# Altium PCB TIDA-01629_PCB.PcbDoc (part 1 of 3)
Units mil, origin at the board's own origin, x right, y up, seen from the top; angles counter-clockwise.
Board outline 2351.88 x 2559.06 mil, 4 copper layers (Top Layer, GND, POWER, Bottom Layer), stack 60.63 mil thick; 223 components, 122 nets, 655 pads, 542 vias.
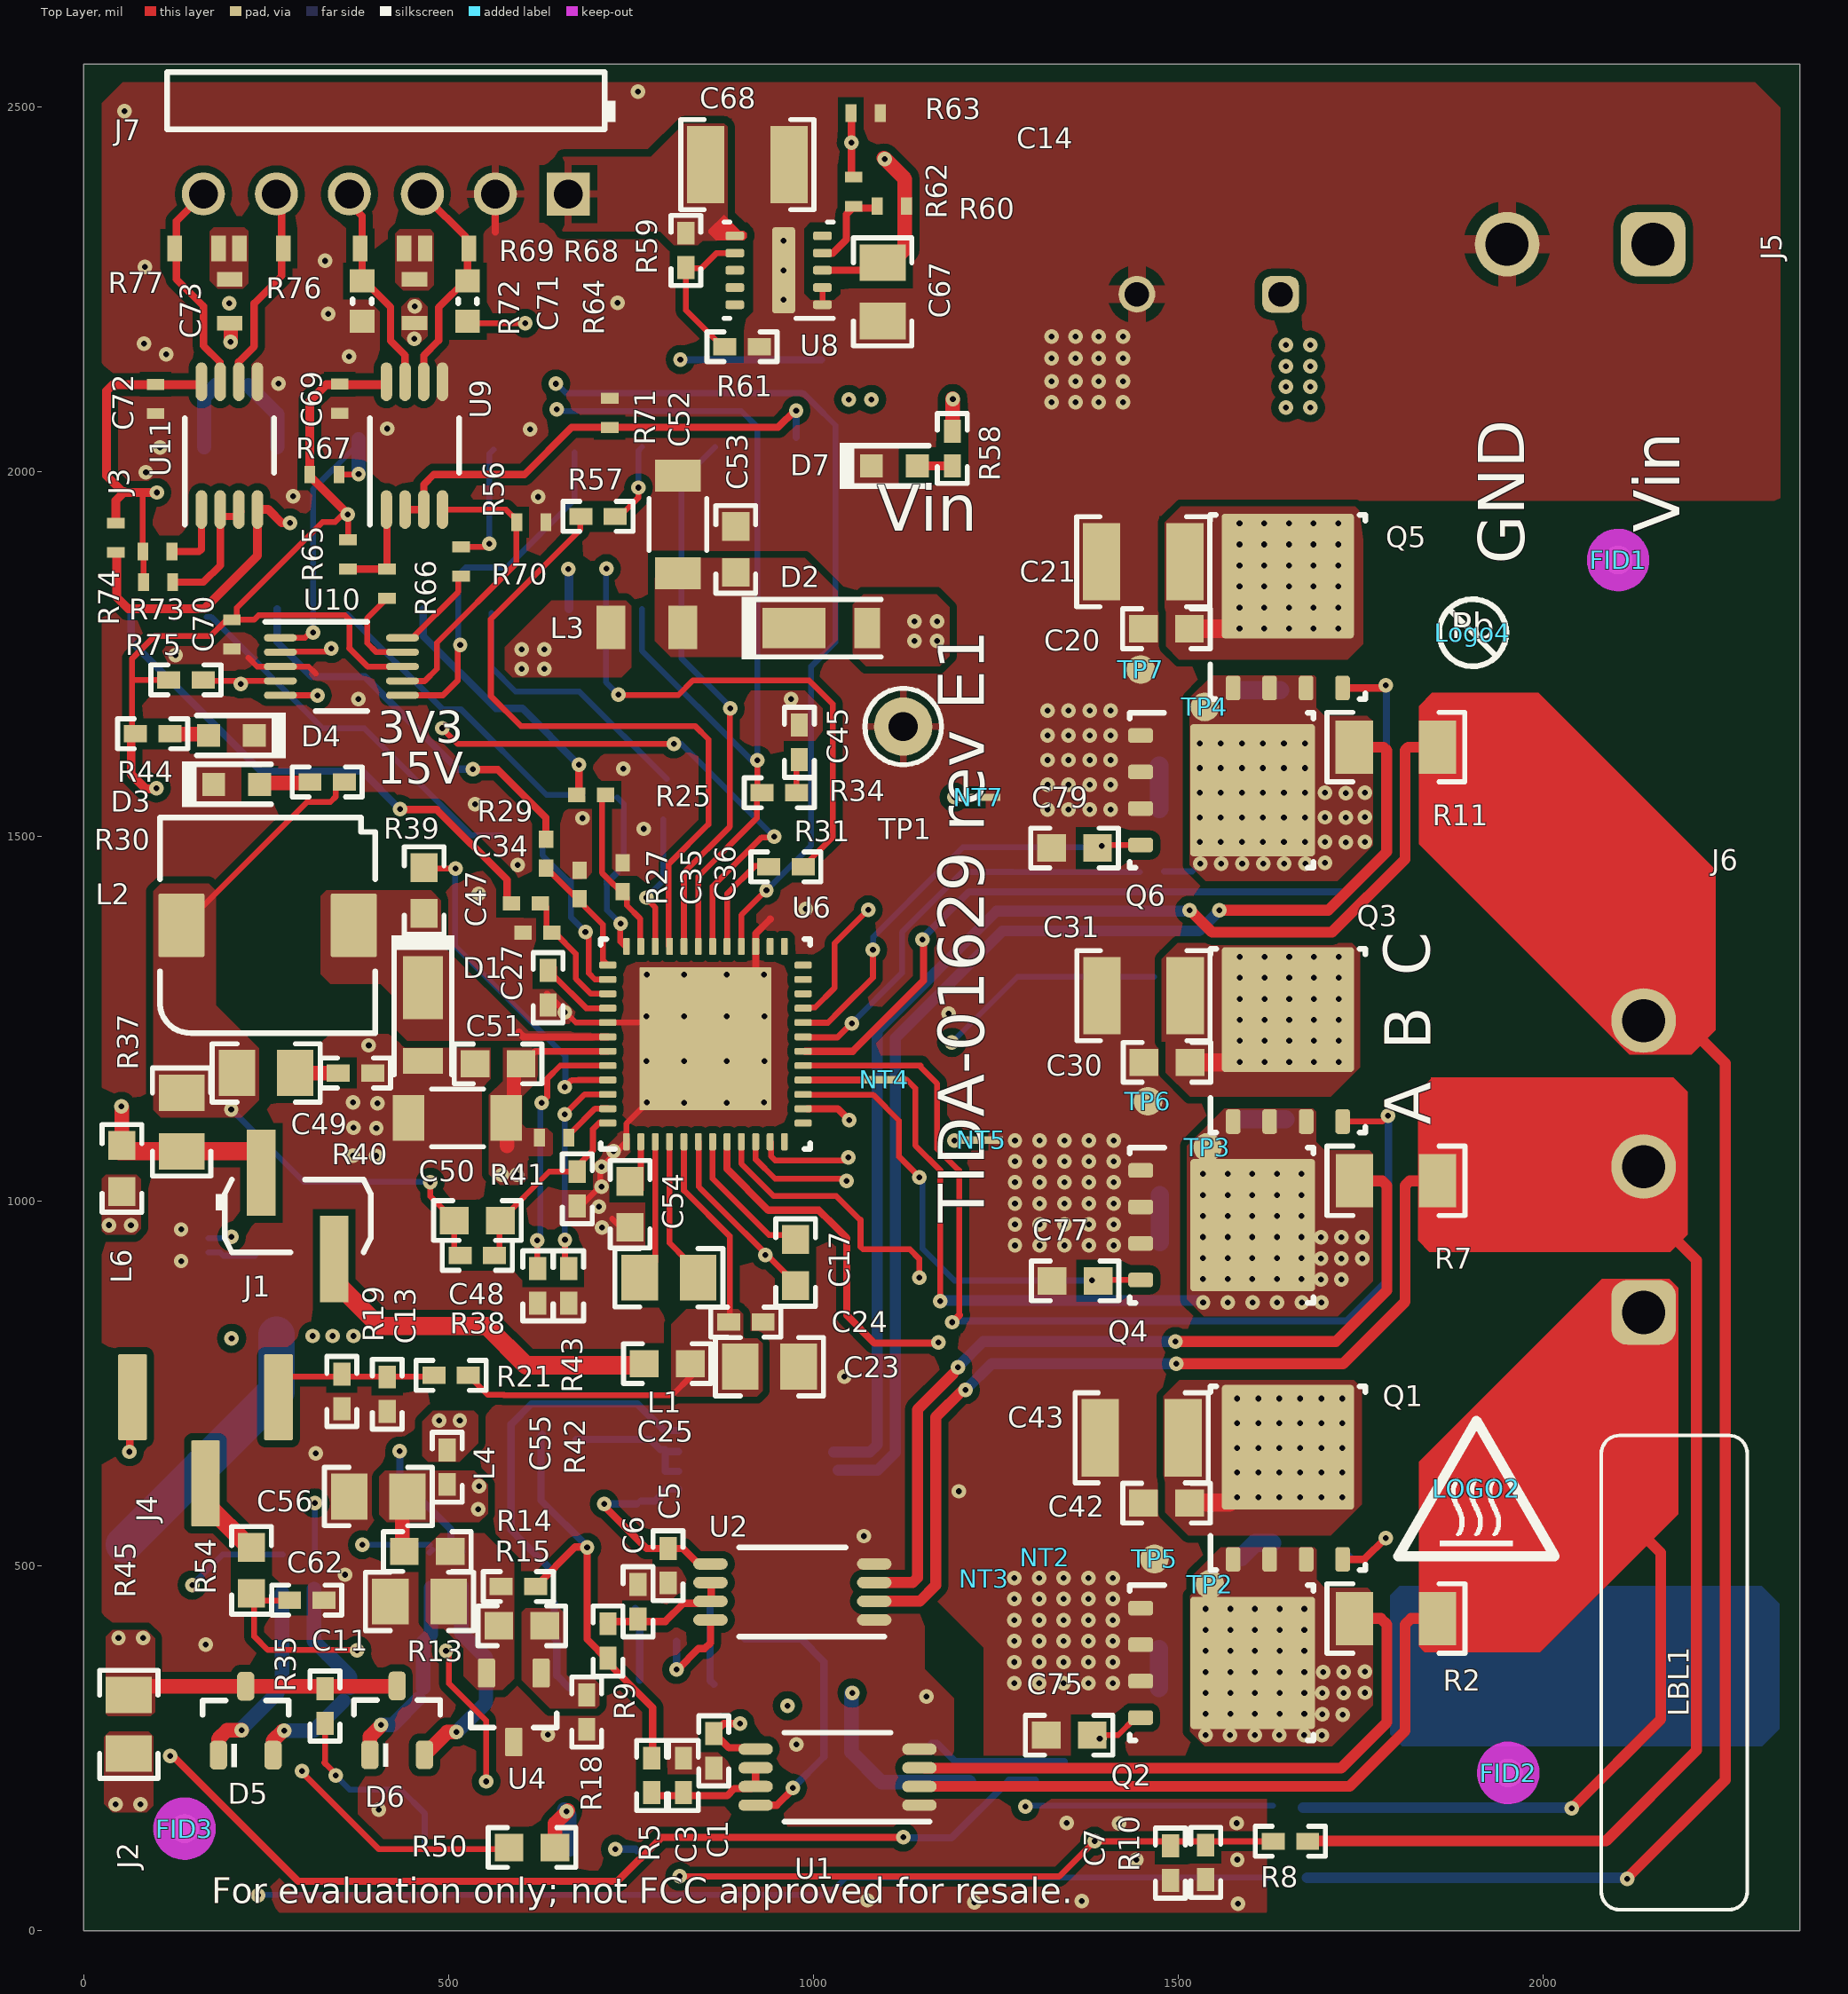
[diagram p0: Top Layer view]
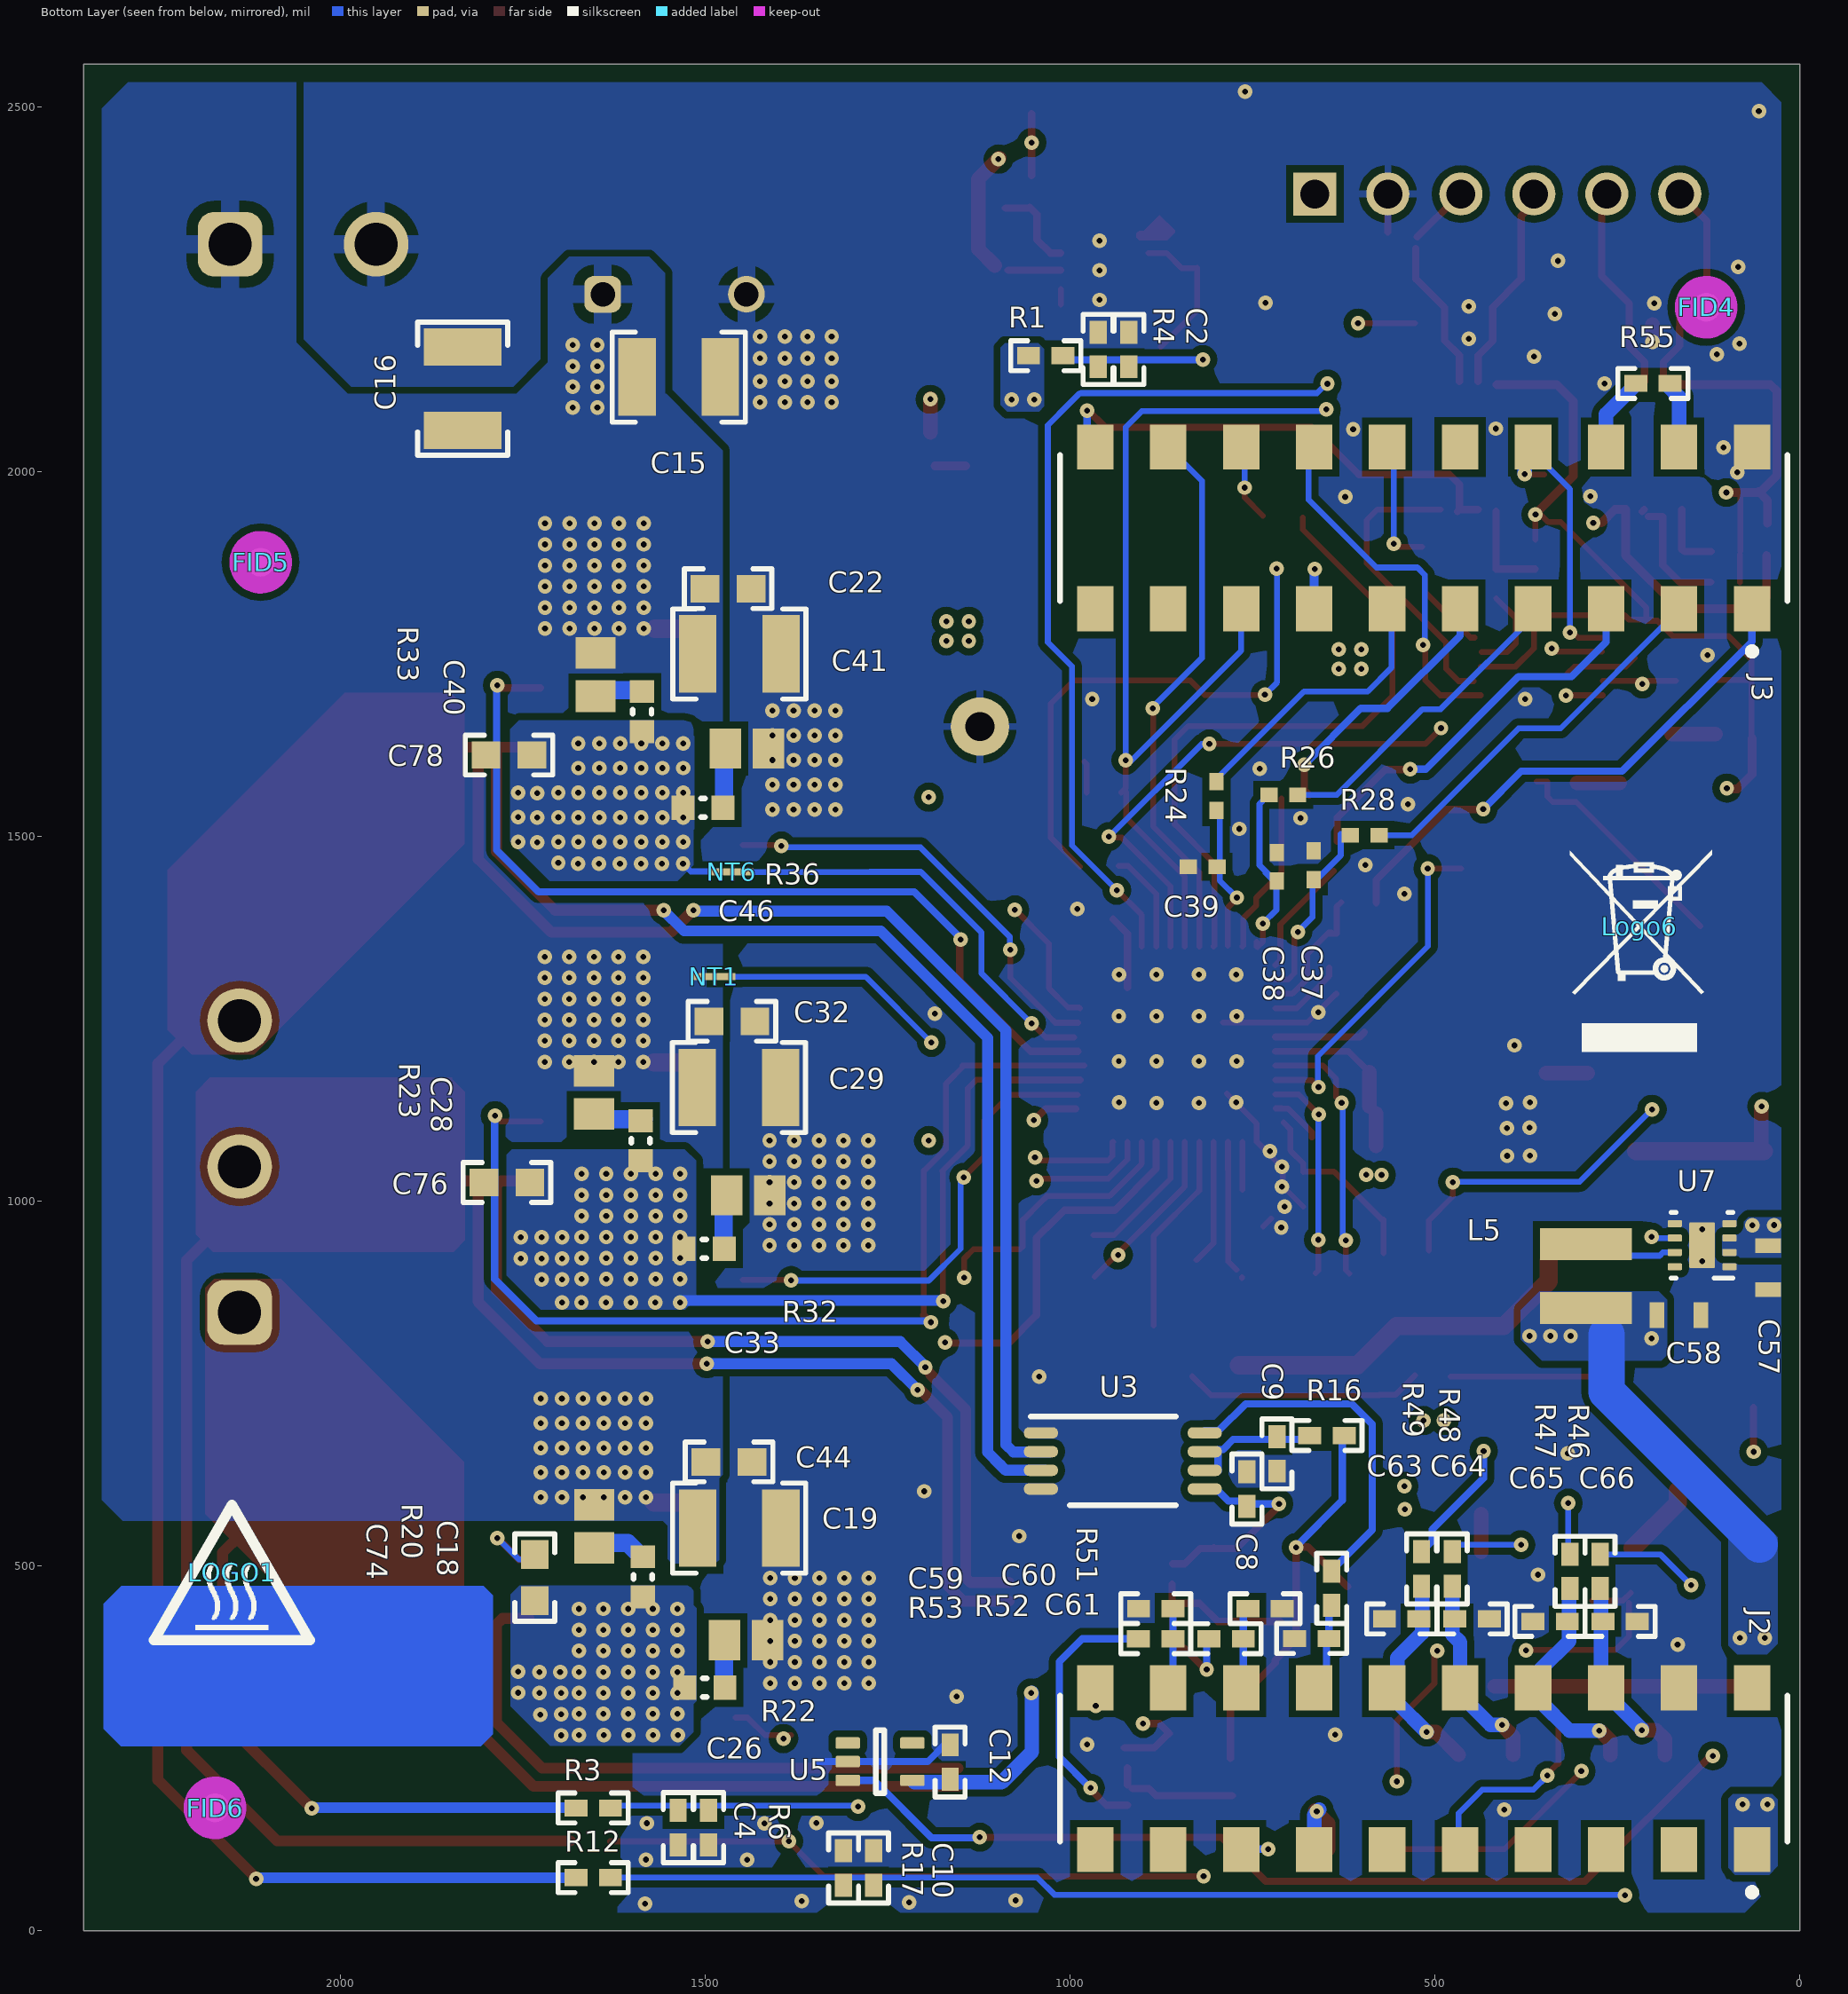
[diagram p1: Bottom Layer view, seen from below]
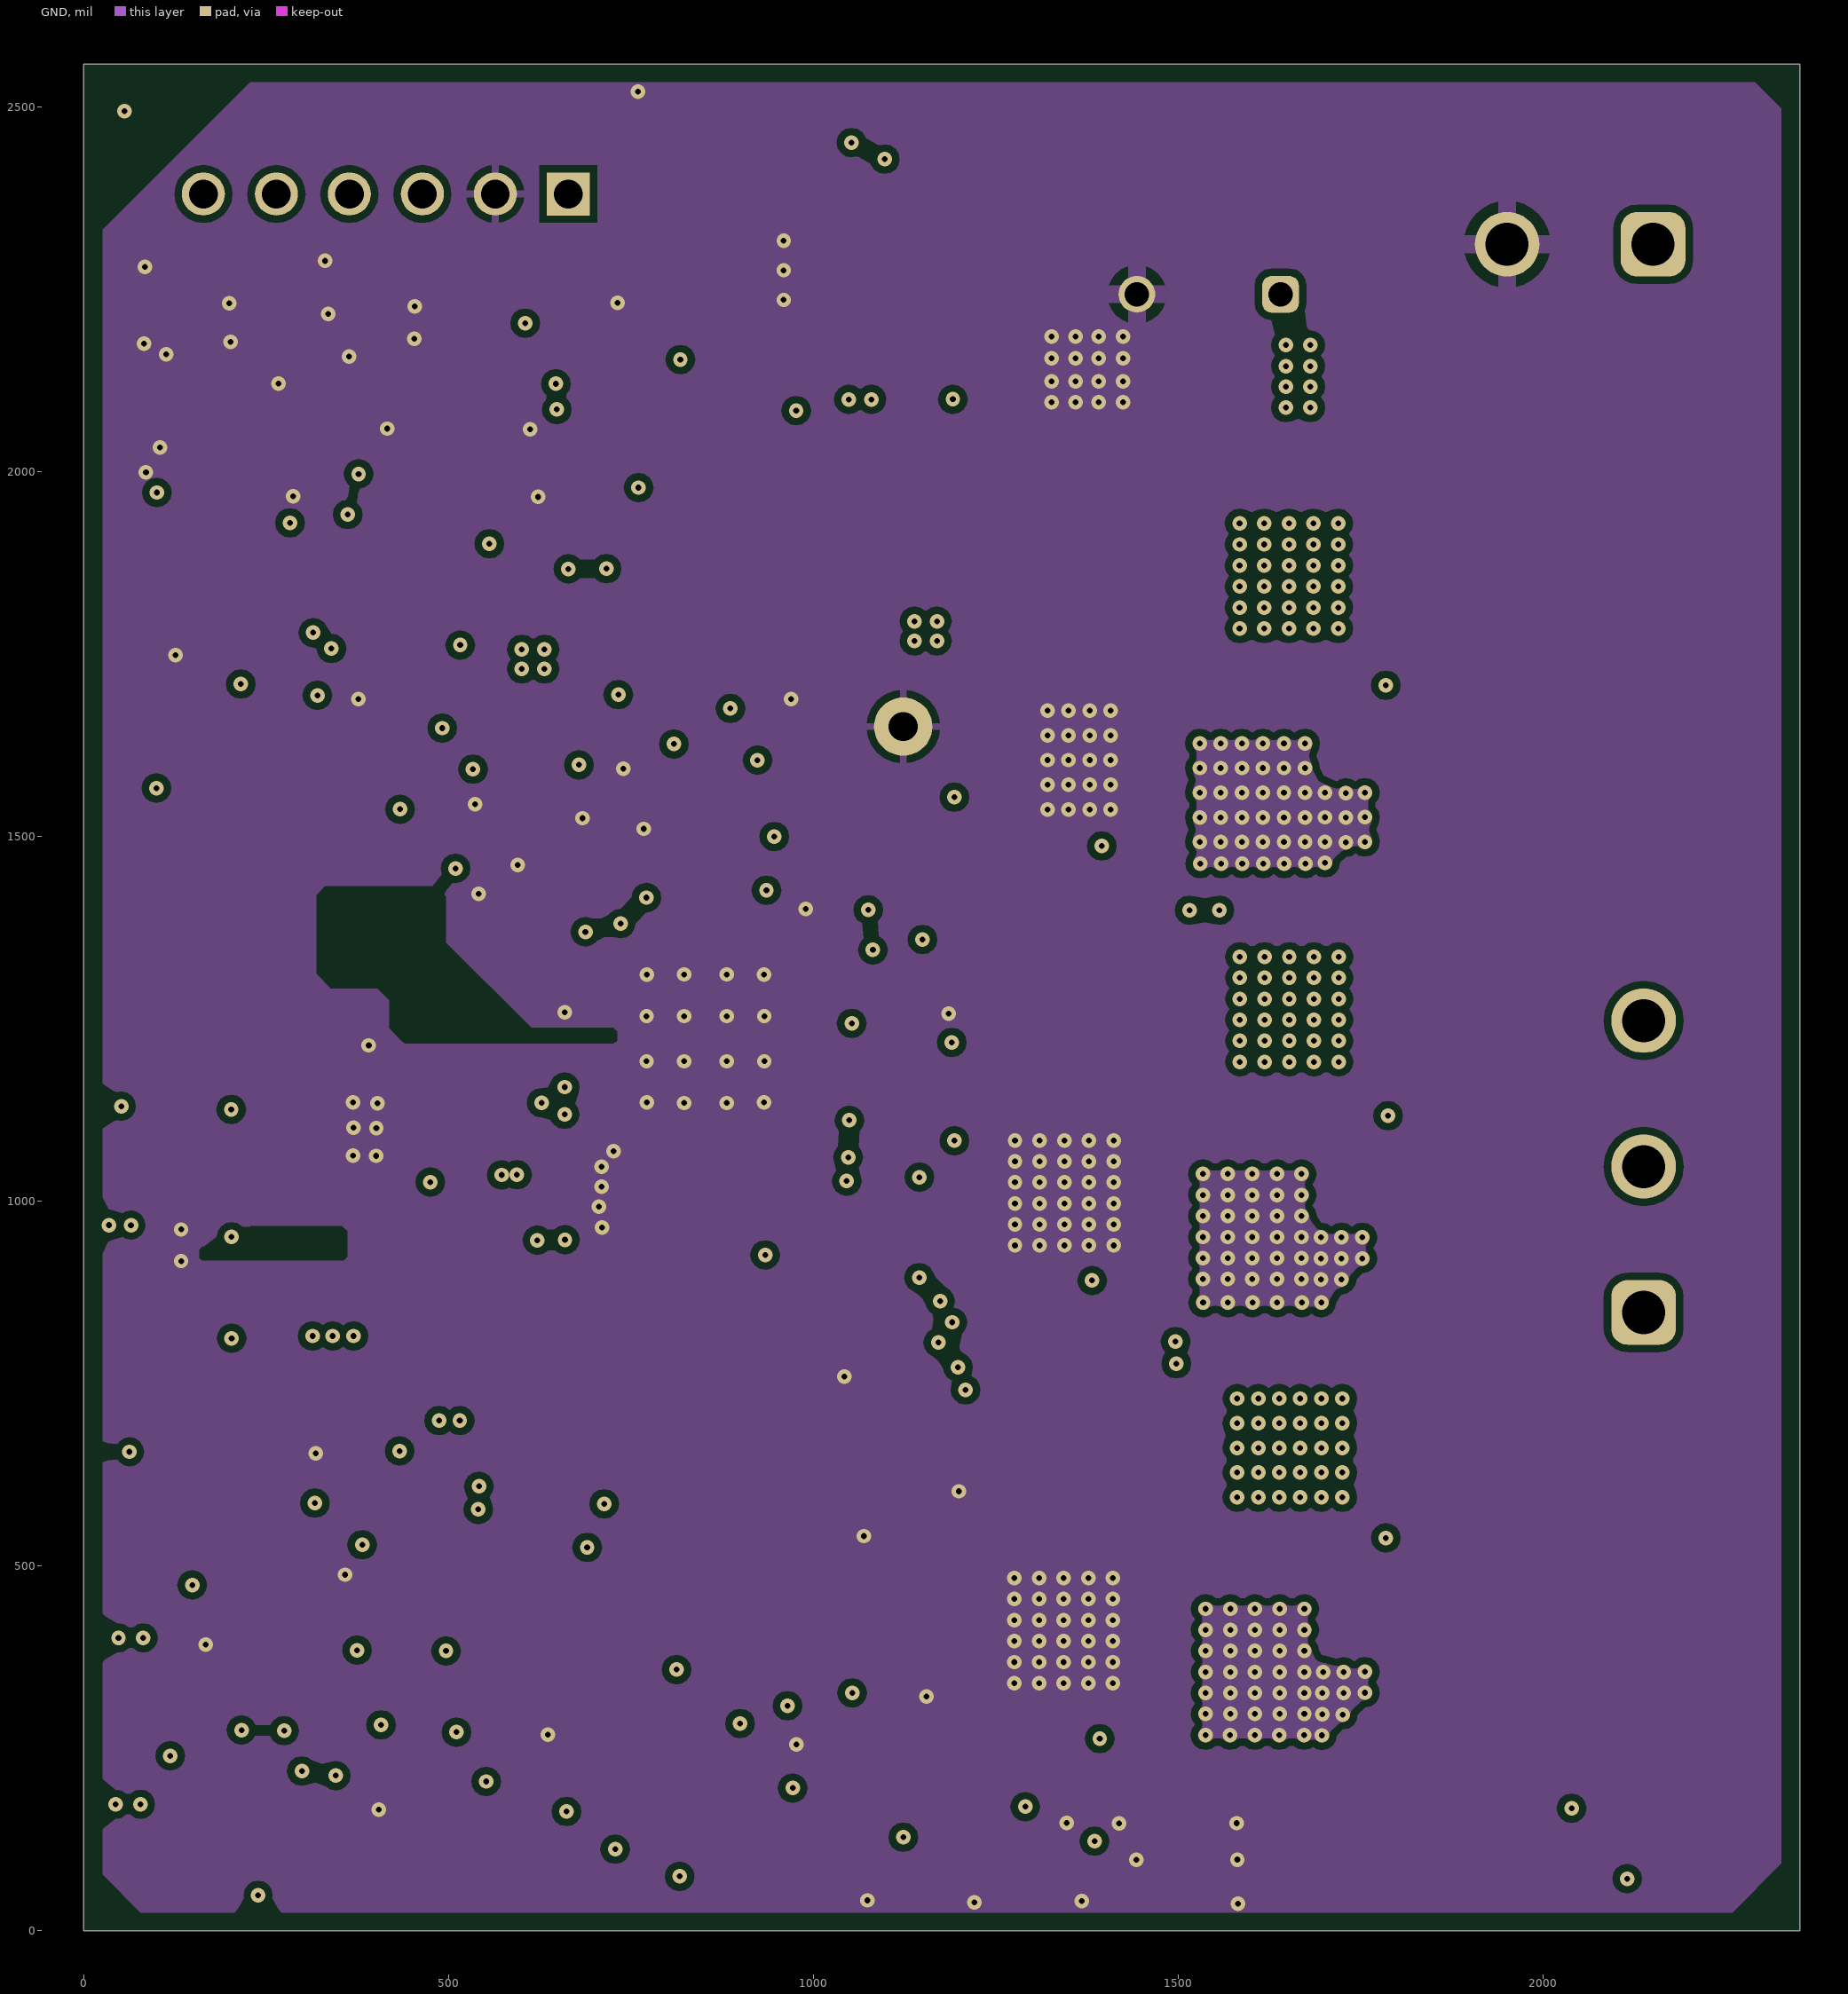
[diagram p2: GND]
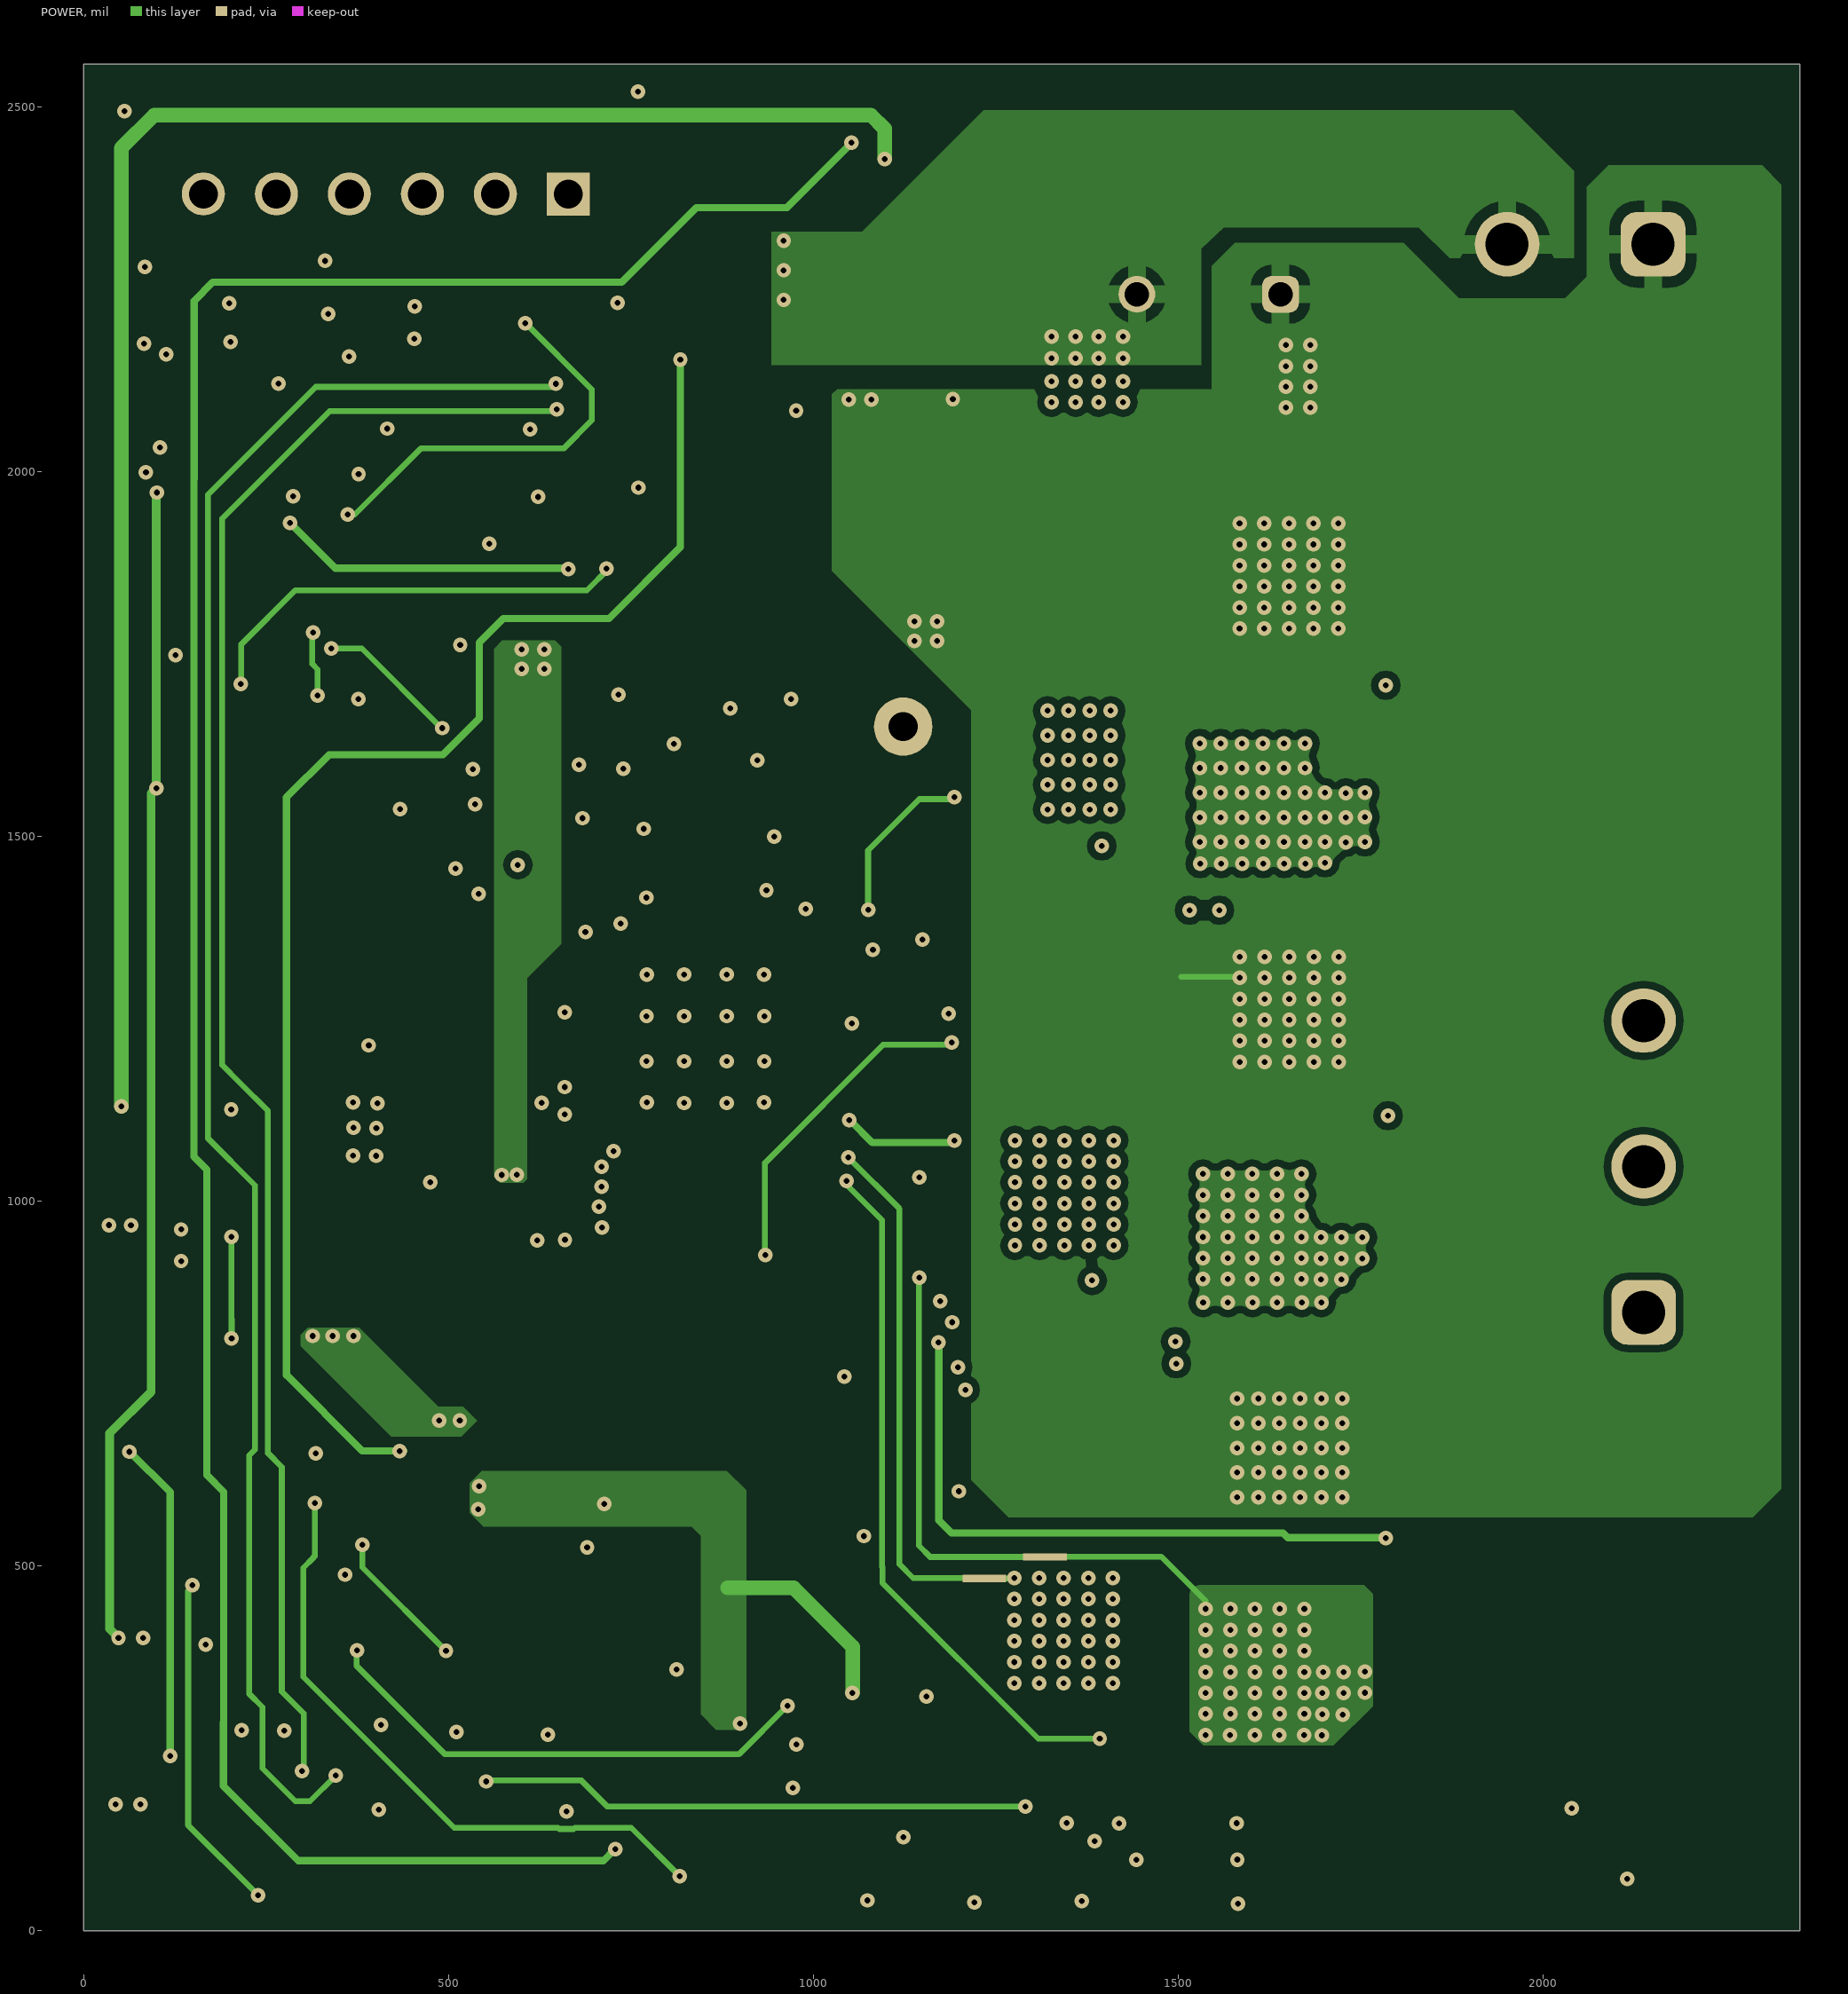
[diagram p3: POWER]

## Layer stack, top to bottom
Top Solder: solder mask 0.9843, Solder Resist, Dk 3.5
Top Layer: signal copper 2.7559
Dielectric 2: prepreg 14.9606, FR-4, Dk 4.2
GND: signal copper 2.7559
Dielectric1: core 19.685, FR-4, Dk 4.2
POWER: signal copper 2.7559
Dielectric 3: prepreg 14.9606, FR-4, Dk 4.2
Bottom Layer: signal copper 2.7559
Bottom Solder: solder mask 0.9843, Solder Resist, Dk 3.5

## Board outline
0,0 2351.88,0 2351.88,2559.06 0,2559.06

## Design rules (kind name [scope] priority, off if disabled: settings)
AcuteAngle [All] p1: minimum=6.90000000000000E+0001 checktracksonly=FALSE
AssemblyTestPointUsage [All] p1: valid=2
BoardOutlineClearance BoardOutlineClearance_MountingHoles [OnCopper and InComponentClass('Mounting Holes')] p1: gap=40 ignorepadtopadclearanceinfootprint=FALSE
BoardOutlineClearance BoardOutlineClearance_Poly [OnCopper and IsPoly] p2: gap=25 ignorepadtopadclearanceinfootprint=FALSE
BoardOutlineClearance [OnCopper and Not InComponentClass('Logo') and not InComponentClass('FiducialMark') and not InRegion(1000,500,4000,800) and not InPoly] p3: gap=25 ignorepadtopadclearanceinfootprint=FALSE
Clearance Clearance_TP [(ObjectKind = 'Component') And (Comment = 'TP_SM_1MM')] p1: gap=0 ignorepadtopadclearanceinfootprint=TRUE
Clearance Clearance_NetTie [(ObjectKind = 'Component') And (Comment = 'Net-Tie')] p2: gap=9.84 ignorepadtopadclearanceinfootprint=FALSE except(0: Arc-Hole Track-Hole SMDPad-Hole THPad-Hole Via-Hole Fill-Hole Poly-Hole Region-Hole Text-Hole)
Clearance Clearance_Keepouts [((IsTrack Or IsArc) And Not InPoly) And IsFree and IsKeepOut vs ((IsTrack Or IsArc) And Not InPoly) And IsFree and IsKeepOut] p3: gap=0 ignorepadtopadclearanceinfootprint=FALSE
Clearance Clearance_Poly [InPolygon] p4: gap=9.84 ignorepadtopadclearanceinfootprint=FALSE except(0: Arc-Hole Track-Hole SMDPad-Hole THPad-Hole Via-Hole Fill-Hole Poly-Hole Region-Hole Text-Hole)
Clearance Clearance_FiducialMark [IsKeepOut and InComponentClass('FiducialMark') vs IsPad and InComponentClass('FiducialMark')] p5: gap=0 ignorepadtopadclearanceinfootprint=FALSE
Clearance [All] p6: gap=9.84 ignorepadtopadclearanceinfootprint=FALSE except(0: Arc-Hole Track-Hole SMDPad-Hole THPad-Hole Via-Hole Fill-Hole Poly-Hole Region-Hole Text-Hole)
ComponentClearance ComponentClearance_MountingHoles_FiducialMarks [InComponentClass('Mounting Holes') vs InComponentClass('FiducialMark')] p1: gap=50 collisioncheckmode=3 verticalgap=10 showdistances=FALSE
ComponentClearance ComponentClearance_Shunt [InComponentClass('Header') vs InComponentClass('Shunt')] p2: gap=0 collisioncheckmode=3 verticalgap=0 showdistances=FALSE
ComponentClearance ComponentClearance_Logo [InComponentClass('Logo')] p3: gap=50 collisioncheckmode=3 verticalgap=10 showdistances=FALSE
ComponentClearance ComponentClearance_ScrewToNut [(HasFootprint('NY PMS 440 0025 PH')) vs (HasFootprint('Keystone_1902C'))] p4: gap=5 collisioncheckmode=3 verticalgap=10 showdistances=FALSE
ComponentClearance ComponentClearance_MountingHoles [InComponentClass('Mounting Holes')] p5: gap=250 collisioncheckmode=3 verticalgap=100000 showdistances=FALSE
ComponentClearance ComponentClearance_SmallPassives [HasFootprint('0201*') or HasFootprint('0402*') or HasFootprint('0508') or HasFootprint('0603*') or HasFootprint('0612') or HasFootprint('0805*') or HasFootprint('0815*') or HasFootprint('0830*') or HasFootprint('1206*') or HasFootprint('1210*') or HasFootprint('1808*') or HasFootprint('1812*') or HasFootprint('1825*') or HasFootprint('2010*') or HasFootprint('2220*') or HasFootprint('2225*') or HasFootprint('2512*') or HasFootprint('2728*') or HasFootprint('3518*') vs HasFootprint('0201*') or HasFootprint('0402*') or HasFootprint('0508') or HasFootprint('0603*') or HasFootprint('0612') or HasFootprint('0805*') or HasFootprint('0815*') or HasFootprint('0830*') or HasFootprint('1206*') or HasFootprint('1210*') or HasFootprint('1808*') or HasFootprint('1812*') or HasFootprint('1825*') or HasFootprint('2010*') or HasFootprint('2220*') or HasFootprint('2225*') or HasFootprint('2512*') or HasFootprint('2728*') or HasFootprint('3518*')] p6: gap=14.96 collisioncheckmode=3 verticalgap=10 showdistances=FALSE
ComponentClearance ComponentClearance_THtoSMT [IsThruComponent vs IsSMTComponent] p7: gap=40 collisioncheckmode=3 verticalgap=30 showdistances=FALSE
ComponentClearance ComponentClearance_THtoTH [IsThruComponent vs IsThruComponent] p8: gap=30 collisioncheckmode=3 verticalgap=30 showdistances=FALSE
ComponentClearance ComponentClearance_TP [(ObjectKind = 'Component') And (Comment = 'TP_SM_1MM')] p9: gap=0 collisioncheckmode=3 verticalgap=0 showdistances=FALSE
ComponentClearance [All] p10: gap=30 collisioncheckmode=3 verticalgap=10 showdistances=FALSE
DiffPairsRouting [All] p1 off: maxlimit=100 minlimit=10 mostfreqgap=10 toplayer_minwidth=7 toplayer_maxwidth=25 toplayer_prefwidth=15 midlayer1_minwidth=7 midlayer1_maxwidth=25 midlayer1_prefwidth=15 midlayer2_minwidth=7 midlayer2_maxwidth=25 midlayer2_prefwidth=15 bottomlayer_minwidth=7 bottomlayer_maxwidth=25 bottomlayer_prefwidth=15 maxuncoupledlength=1000
FabricationTestPointUsage TestPointUsage [All] p1: valid=2 allowmultiple=FALSE
FabricationTestpoint Testpoint [All] p1: side=3 testpointundercomponent=TRUE minsize=40 maxsize=100 preferedsize=60 minholesize=0 maxholesize=40 preferedholesize=32 testpointgrid=1 allowsidetop=TRUE allowsidebottom=TRUE usegrid=TRUE gridtolerance=0.01
FanoutControl Fanout_LCC [IsLCC] p1: bgadir=Out bgaviamode=Centered fanoutstyle=Auto fanoutdirection=Alternating viagrid=1 // Fanout_LCC (Default Rule)
FanoutControl Fanout_BGA [IsBGA] p2: bgadir=Out bgaviamode=Centered fanoutstyle=Auto fanoutdirection=Alternating viagrid=1 // Fanout_BGA (Default Rule)
FanoutControl Fanout_Default [All] p4: bgadir=Out bgaviamode=Centered fanoutstyle=Auto fanoutdirection=Alternating viagrid=1 // Fanout_Default (Default Rule)
FanoutControl Fanout_Small [(CompPinCount < 5)] p5: bgadir=Out bgaviamode=Centered fanoutstyle=Auto fanoutdirection=OutThenIn viagrid=1 // Fanout_Small (Default Rule)
Height [All] p1: minheight=0 maxheight=1050 prefheight=500
HoleSize [All] p1: absolutevalues=TRUE maxlimit=251 minlimit=7.87 maxpercent=80.000 minpercent=20.000
MinimumAnnularRing MinimumAnnularRing_ThermalPadVias [IsVia and InAnyComponent] p1: minimumring=5.91
MinimumAnnularRing [All] p2: minimumring=5.91
MinimumSolderMaskSliver MinimumSolderMaskSliver_Logo [InComponentClass('Logo') vs InComponentClass('Logo')] p1: minsoldermaskwidth=0.7
MinimumSolderMaskSliver [All] p2: minsoldermaskwidth=2.72
PlaneConnect [All] p1: planeconnectstyle=Relief reliefexpansion=10 reliefentries=4 reliefconductorwidth=10 reliefairgap=10
PolygonConnect "Thermal Connect" [IsVia] p1 off: thpad.connectstyle=Relief thpad.reliefconductorwidth=10 thpad.reliefentries=4 thpad.polygonreliefangle="90 Angle" thpad.airgapwidth=10 smdpad.connectstyle=Direct smdpad.reliefconductorwidth=10 smdpad.reliefentries=4 smdpad.polygonreliefangle="90 Angle" smdpad.airgapwidth=10 via.connectstyle=Direct via.reliefconductorwidth=10 via.reliefentries=4 via.polygonreliefangle="90 Angle" via.airgapwidth=10
PolygonConnect PolygonConnect_Thermal [((ObjectKind = 'Poly') And ((Net = 'PH_C_P') or (Net = 'PH_B_P') or (Net = 'PH_A_P') or (Name = 'BOTTOM_LAYER_VIN_P286') or (Name = 'BOTTOM_LAYER_VIN_P284') or (Name = 'POWER_VIN_P288') or (Name = 'POWER_VIN_P294') or (Name = 'THERMAL_GND')))] p2 off: connectstyle=Relief reliefconductorwidth=20 reliefentries=4 polygonreliefangle="90 Angle" airgapwidth=10
PolygonConnect "Thermal Connect_HighCurrent" [IsThruPin and InComponent('C14','J5')] p3: connectstyle=Relief reliefconductorwidth=25 reliefentries=4 polygonreliefangle="90 Angle" airgapwidth=15
PolygonConnect [All] p4: thpad.connectstyle=Relief thpad.reliefconductorwidth=10 thpad.reliefentries=4 thpad.polygonreliefangle="90 Angle" thpad.airgapwidth=10 smdpad.connectstyle=Direct smdpad.reliefconductorwidth=10 smdpad.reliefentries=4 smdpad.polygonreliefangle="90 Angle" smdpad.airgapwidth=10 via.connectstyle=Direct via.reliefconductorwidth=10 via.reliefentries=4 via.polygonreliefangle="90 Angle" via.airgapwidth=10
RoutingVias ThermalPadVias [IsVia and InAnyComponent] p1: holewidth=7.87 width=19.68 viastyle="Through Hole" minholewidth=7.87 minwidth=19.68 maxholewidth=12.99 maxwidth=23.62
RoutingVias [All] p2: holewidth=16 width=34 viastyle="Through Hole" minholewidth=7.87 minwidth=19.68 maxholewidth=40 maxwidth=65
SilkToBoardRegionClearance [Not ((IsComment or IsDesignator) And (Hide <> 'False')) and not InRegion(1000,500,4000,800)] p1:
SilkToSilkClearance SilkToSilkClearance_Pb-FreeLogo [(HasFootprint('Pb-Free_Overlay_Medium') OR HasFootprint('Pb-Free_Overlay_Small')) vs (HasFootprint('Pb-Free_Overlay_Medium') OR HasFootprint('Pb-Free_Overlay_Small'))] p1: silktosilkclearance=0
SilkToSilkClearance [All] p2: silktosilkclearance=4
SilkToSolderMaskClearance SilkToComponentPadClearance [(IsPad or IsFill or IsRegion) and InAnycomponent] p1: minsilkscreentomaskgap=5 clearancetoexposedcopper=TRUE
SilkToSolderMaskClearance "Silk to Solder Mask Opening" [All] p2: minsilkscreentomaskgap=4 clearancetoexposedcopper=FALSE
SolderMaskExpansion [All] p1: expansion=1.97
Width [All] p1: maxlimit=100 minlimit=7.87 preferedwidth=10 checkconnectedcopper=TRUE
14 further rules are at their usual default settings.

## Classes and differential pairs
component class TIDA-01629_EVM_Hardware: FID1 FID2 FID3 FID4 FID5 FID6 LBL1 LOGO1 LOGO2 Logo4 Logo5 Logo6 ZZ1 ZZ2 ZZ3 ZZ4
component class FiducialMark: FID1 FID2 FID3 FID4 FID5 FID6
component class AssemblyNote: ZZ1 ZZ2 ZZ3 ZZ4
component class Label: LBL1
component class Header: J1 J4 J7
component class TIDA-01629_CurrentSense: C1 C2 C3 C4 C5 C6 C7 C8 C9 C10 C11 C12 R1 R2 R3 R4 R5 R6 R7 R8 R9 R10 R11 R12 R13 R14 R15 R16 R17 R18 U1 U2 U3 U4 U5
component class TIDA-01629_Gate_Driver: C13 C14 C15 C16 C17 C18 C19 C20 C21 C22 C23 C24 C25 C26 C27 C28 C29 C30 C31 C32 C33 C34 C35 C36 C37 C38 C39 C40 C41 C42 C43 C44 C45 C46 C47 C48 C49 C50 C51 C52 C53 C54 C55 C56 C57 C58 C74 C75 C76 C77 C78 C79 D1 D2 D3 D4 J1 L1 L2 L3 L4 L5 L6 NT1 NT2 NT3 NT4 NT5 NT6 NT7 Q1 Q2 Q3 Q4 Q5 Q6 R19 R20 R21 R22 R23 R24 R25 R26 R27 R28 R29 R30 R31 R32 R33 R34 R35 R36 R37 R38 R39 R40 R41 R42 R43 R44 TP1 TP2 TP3 TP4 TP5 TP6 TP7 TP? U6 U7
component class TIDA-01629_Interface: C59 C60 C61 C62 C63 C64 C65 C66 D5 D6 D7 J2 J3 J4 J5 J6 R45 R46 R47 R48 R49 R50 R51 R52 R53 R54 R55 R56 R57 R58
component class TIDA-01629_Encoder: C67 C68 C69 C70 C71 C72 C73 J7 R59 R60 R61 R62 R63 R64 R65 R66 R67 R68 R69 R70 R71 R72 R73 R74 R75 R76 R77 U8 U9 U10 U11
differential pair PH_C: +PH_C_P -PH_C_N
differential pair PH_B: +PH_B_P -PH_B_N
differential pair PH_A: +PH_A_P -PH_A_N
differential pair CLK: +CLK_P -CLK_N
differential pair DATA: +DATA_P -DATA_N

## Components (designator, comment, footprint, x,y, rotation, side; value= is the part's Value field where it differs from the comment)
C1 "885012205037" 0402 863.72,247 r270 top value=0.1uF
C2 "GRM155R71A104KA01D" 0402 919.24,2167.56 r90 bottom value=0.1uF
C3 "885012205037" 0402 822.2,213.25 r90 top value=0.1uF
C4 "GRM155R71A104KA01D" 0402 1536.97,141.62 r270 bottom value=0.1uF
C5 "885012205037" 0402 801,500.66 r270 top value=0.1uF
C6 "885012205037" 0402 759.93,451.14 r90 top value=0.1uF
C7 "GRM155R71A104KA01D" 0402 1489.46,93.06 r270 top value=0.1uF
C8 "885012205037" 0402 757.42,605.64 r90 bottom value=0.1uF
C9 "885012205037" 0402 716.52,653.91 r270 bottom value=0.1uF
C10 "GRM155R71A104KA01D" 0402 1269.15,86.27 r90 bottom value=0.1uF
C11 "885012207103" 0805_HV 460.53,451.64 r180 top value=1uF
C12 "885012205037" 0402 1164.21,231.51 r90 bottom value=0.1uF
C13 "GCM155R71H223KA55D" 0402 416.26,735.68 r90 top value=0.022uF
C14 "EKYB101ELL181MK20S" KYB_1250x2000 1541.92,2243.25 r180 top value=180uF
C15 "GRM32ER72A105KA01L" 1210_270 1536.16,2129.83 r180 bottom value=1uF
C16 "GRM32ER72A105KA01L" 1210_270 1832.33,2114.02 r90 bottom value=1uF
C17 "GRM188R61H105KAALD" 0603 975.86,916.1 r270 top value=1uF
C18 "GRM188R72A222KA01D" 0603L 1585.43,485.38 r270 bottom value=2200pF
C19 "GRM32ER72A225KA35L" 1210_270 1453.27,552.19 r180 bottom value=2.2uF
C20 "GRM188R72A104KA35J" 0603 1484.02,1784.92 r180 top value=0.1uF
C21 "GRM32ER72A225KA35L" 1210_270 1452.15,1876.71 r180 top value=2.2uF
C22 "GRM188R72A104KA35J" 0603 1468.56,1839.62 r180 bottom value=0.1uF
C23 "GRM21BZ71E106KE15L" 0805_HV 940.05,773.41 r0 top value=10uF
C24 "GRM155R71E104KE14D" 0402 907.72,834.44 r0 top value=0.1uF
C25 "GRM21BR72A473KA01L" 0805_HV 802.35,895.47 r180 top value=0.047uF
C26 "GRM188R72A222KA01D" 0603L 1500.35,333.63 r180 bottom value=2200pF
C27 "GRM155R70J105MA12D" 0402 636.72,1293.01 r270 top value=1uF
C28 "GRM188R72A222KA01D" 0603L 1588.47,1083.09 r270 bottom value=2200pF
C29 "GRM32ER72A225KA35L" 1210_270 1453.54,1156.05 r180 bottom value=2.2uF
C30 "GRM188R72A104KA35J" 0603 1484.8,1190.55 r180 top value=0.1uF
C31 "GRM32ER72A225KA35L" 1210_270 1452.65,1282.02 r180 top value=2.2uF
C32 "GRM188R72A104KA35J" 0603 1463.26,1246.82 r180 bottom value=0.1uF
C33 "GRM188R72A222KA01D" 0603L 1501.28,935.11 r180 bottom value=2200pF
C34 "885012005044" 0402L 622.11,1368.42 r180 top value=47pF
C35 "885012005044" 0402L 680.06,1434.3 r90 top value=47pF
C36 "885012005044" 0402L 738.93,1444.5 r90 top value=47pF
C37 "885012005044" 0402L 666.21,1460.65 r90 bottom value=47pF
C38 "885012005044" 0402L 716.64,1458.61 r90 bottom value=47pF
C39 "885012005044" 0402L 818.18,1458.58 r0 bottom value=47pF
C40 "GRM188R72A222KA01D" 0603L 1586.25,1671.25 r270 bottom value=2200pF
C41 "GRM32ER72A225KA35L" 1210_270 1453.02,1750.34 r180 bottom value=2.2uF
C42 "GRM188R72A104KA35J" 0603 1484.19,586.51 r180 top value=0.1uF
C43 "GRM32ER72A225KA35L" 1210_270 1450.11,675.87 r180 top value=2.2uF
C44 "GRM188R72A104KA35J" 0603 1467.25,642.91 r180 bottom value=0.1uF
C45 "885012005061" 0402 980.97,1629.17 r90 top value=100pF
C46 "GRM188R72A222KA01D" 0603L 1502.87,1539.6 r180 bottom value=2200pF
C47 "GRM188R72A103KA01D" 0603 466.82,1426.13 r90 top value=0.01uF
C48 "GRM1885C1H302JA01D" 0603 539.82,973.77 r0 top value=3000pF
C49 "C2012X7R1H225K125AC" 0805_HV 250.31,1176.07 r0 top value=2.2uF
C50 "Capacitor" 1206_190 512.55,1114.42 r180 top value=3.3uF
C51 "GRM188R72A104KA35J" 0603 568.1,1188.58 r180 top value=0.1uF
C52 "Capacitor" 1206_190 814.65,1927.83 r90 top value=3.3uF
C53 "Capacitor" 0603 893.94,1893.57 r90 top value=0.1uF
C54 "UMK107AB7105KA-T" 0603 748.98,996.08 r270 top value=1uF
C55 "885012205037" 0402 622.66,884.33 r270 top value=0.1uF
C56 "885012207026" 0805_HV 404.1,595.46 r180 top value=10uF
C57 "Capacitor" 0603S 43.33,909.13 r270 bottom value=10uF
C58 "Capacitor" 0603S 165.53,843.98 r180 bottom value=22uF
C59 "GRM155R71C222KA01D" 0402 882.46,441.81 r0 bottom value=2200pF
C60 "GRM155R71C222KA01D" 0402 732.72,441.81 r180 bottom value=2200pF
C61 "GRM155R71C222KA01D" 0402 668.77,400.81 r0 bottom value=2200pF
C62 "GRM155R71C222KA01D" 0402 306.05,453.54 r0 top value=2200pF
C63 "GRM155R71C222KA01D" 0402 545.46,427.68 r0 bottom value=2200pF
C64 "GRM155R71C222KA01D" 0402 449.11,427.68 r180 bottom value=2200pF
C65 "GRM155R71C222KA01D" 0402 342.18,424.36 r0 bottom value=2200pF
C66 "GRM155R71C222KA01D" 0402 246.16,424.34 r180 bottom value=2200pF
C67 "GRM21BZ71E106KE15L" 0805_HV 1095.22,2246.68 r270 top value=10uF
C68 "GRM32ER71E226KE15L" 1210_270 909.88,2421.05 r0 top value=22uF
C69 "Capacitor" 0402S 351.06,2100.23 r270 top value=0.1uF
C70 "Capacitor" 0402S 203.34,1777.12 r270 top value=0.1uF
C71 "Capacitor" 0603S 453.51,2233.9 r270 top value=470pF
C72 "Capacitor" 0402S 98.82,2099.87 r270 top value=0.1uF
C73 "Capacitor" 0603S 200.26,2233.58 r270 top value=470pF
C74 "GRM1885C1E102JA01D" 0603 1733.44,484.45 r270 bottom value=1000pF
C75 "GRM1885C1E102JA01D" 0603 1350.75,268.5 r180 top value=1000pF
C76 "GRM1885C1E102JA01D" 0603 1771.61,1025.88 r180 bottom value=1000pF
C77 "GRM1885C1E102JA01D" 0603 1358.82,890.99 r180 top value=1000pF
C78 "GRM1885C1E102JA01D" 0603 1768.73,1611.75 r180 bottom value=1000pF
C79 "GRM1885C1E102JA01D" 0603 1358.07,1484.37 r180 top value=1000pF
D1 "DFLS1200-7" PowerDI123 465.22,1242.57 r270 top value=200V
D2 "DFLS1200-7" PowerDI123 1023.78,1785.66 r0 top value=200V
D3 "LED_A2_K1" WL-SMCW_GREEN 209.99,1571.67 r0 top value=Green
D4 "LED_A2_K1" WL-SMCW_GREEN 202.77,1638.67 r180 top value=Green
D5 "BAT54C-7-F" SOT-23 222.39,288.3 r90 top value=30V
D6 "BAT54C-7-F" SOT-23 429.9,288.69 r90 top value=30V
D7 "LED_A2_K1" WL-SMCW_GREEN 1111.28,2007.97 r0 top value=Green
FID1 "Fiducial" Fiducial10-20 2102.95,1879.01 r0 top
FID2 "Fiducial" Fiducial10-20 1952.46,216.69 r0 top
FID3 "Fiducial" Fiducial10-20 138.34,140.32 r0 top
FID4 "Fiducial" Fiducial10-20 128.33,2225.51 r180 bottom
FID5 "Fiducial" Fiducial10-20 2109.14,1875.96 r180 bottom
FID6 "Fiducial" Fiducial10-20 2171.61,168.81 r180 bottom
J1 "61000218321" Wurth_61000218321 293.61,980.04 r0 top
J2 "89898-310ALF" FCI_89898-310ALF 515.44,222.45 r0 bottom
J3 "89898-310ALF" FCI_89898-310ALF 515.44,1923.03 r0 bottom
J4 "61000318221" Wurth_61000318221 167.25,676.49 r270 top
J5 "691236510002" Wurth_691236510002 2050.87,2311.85 r180 top
J6 "691236510003" Wurth_691236510003 2137.89,1047.77 r90 top
J7 "90121-0766" Molex_90121-0766 414.41,2380.76 r180 top
L1 "742792620" 0603 799.94,777.55 r0 top value="100 ohm"
L2 "MSS7348-224MEB" MSS7348 252.37,1378.41 r180 top value=220uH
L3 "Inductor_Iron" NLCV25 771.97,1786.75 r180 top value=33uH
L4 "742792711" 0402 498.62,635.68 r270 top value="100 ohm"
L5 "Inductor_Iron" XFL3012 293.25,897.64 r270 bottom value=2.2uH
L6 "742792620" 0603 52.61,1045.18 r270 top value="100 ohm"
LBL1 "Label" Label_650x200 2179.89,354.17 r90 top
LOGO1 "CAUTION HOT SURFACE" IEC_HotSurface_Small 2148.45,491.61 r180 bottom
LOGO2 "CAUTION HOT SURFACE" IEC_HotSurface_Small 1908.81,606.84 r0 top
Logo4 "Pb-Free Symbol" Pb-Free_Overlay_Small 1903.7,1779.38 r0 top
Logo5 "FCC disclaimer" FCC_disclaimer 1519.8,2923.5 r0 top
Logo6 "WEEE logo" WEEE_Minimum 219.65,1377.02 r180 bottom
NT1 "Net-Tie" Net-Tie_10milWide_30milLong#1 1488.23,1307.99 r0 bottom net-tie
NT2 "Net-Tie" Net-Tie_10milWide_30milLong#2 1317.38,512.5 r0 top net-tie
NT3 "Net-Tie" Net-Tie_10milWide_30milLong#2 1234.47,483.07 r0 top net-tie
NT4 "Net-Tie" Net-Tie_10milWide_30milLong#1 1097.09,1166.68 r0 top net-tie
NT5 "Net-Tie" Net-Tie_10milWide_30milLong#1 1230.28,1083.99 r0 top net-tie
NT6 "Net-Tie" Net-Tie_10milWide_30milLong#1 1463.64,1451.74 r0 bottom net-tie
NT7 "Net-Tie" Net-Tie_10milWide_30milLong#1 1226.45,1553.65 r0 top net-tie
Q1 "CSD19532Q5B" DNK0008A 1650.49,620.42 r90 top value=100V
Q2 "CSD19532Q5B" DNK0008A 1559.7,367.48 r0 top value=100V
Q3 "CSD19532Q5B" DNK0008A 1650.49,1220.4 r90 top value=100V
Q4 "CSD19532Q5B" DNK0008A 1559.7,967.41 r0 top value=100V
Q5 "CSD19532Q5B" DNK0008A 1650.36,1814.69 r90 top value=100V
Q6 "CSD19532Q5B" DNK0008A 1559.58,1563.58 r0 top value=100V
R1 "CRCW0402100KFKED" 0402 1033.19,2159.03 r180 bottom value=100k
R2 "CRF1206-FZ-R001ELF" 1206 1798.58,428.33 r0 top value=0.001
R3 "CRCW0402100KFKED" 0402 1653.4,168.48 r180 bottom value=100k
R4 "CRCW04023K40FKED" 0402 961.55,2167.64 r270 bottom value=3.40k
R5 "CRCW04020000Z0ED" 0402 778.56,213.25 r90 top value=0
R6 "CRCW04023K40FKED" 0402 1495.14,141.78 r90 bottom value=3.40k
R7 "CRF1206-FZ-R001ELF" 1206 1798.58,1028.15 r0 top value=0.001
R8 "CRCW0402100KFKED" 0402 1653.91,122.87 r180 top value=100k
R9 "CRCW04020000Z0ED" 0402 718.82,397.47 r270 top value=0
R10 "CRCW04023K40FKED" 0402 1537.89,94.04 r90 top value=3.40k
R11 "CRF1206-FZ-R001ELF" 1206 1798.45,1622.58 r0 top value=0.001
R12 "CRCW0402100KFKED" 0402 1653.4,73.13 r180 bottom value=100k
R13 "CRCW0603301RFKEA" 0603 471.17,520.12 r0 top value=301
R14 "CRCW04020000Z0ED" 0402 596.05,472.14 r180 top value=0
R15 "CRCW06032K10FKEA" 0603 600.69,418.32 r180 top value=2.10k
R16 "CRCW04020000Z0ED" 0402 647.92,679.24 r180 bottom value=0
R17 "CRCW04023K40FKED" 0402 1310.26,86.3 r270 bottom value=3.40k
R18 "CRCW040210K0FKED" 0402 689.62,300.03 r90 top value=10.0k
R19 "CRCW040217K4FKED" 0402 354.1,739.51 r270 top value=17.4k
R20 "CRCW08052R70JNEA" 0805L 1651.94,554.57 r90 bottom value=2.7
R21 "CRCW0402100KFKED" 0402 503.84,761.47 r180 top value=100k
R22 "CRCW08052R70JNEA" 0805L 1443.85,398.6 r0 bottom value=2.7
R23 "CRCW08052R70JNEA" 0805L 1652.4,1149.3 r90 bottom value=2.7
R24 "CRCW040220R0FKED" 0402L 799.1,1555.55 r270 bottom value=20.0
R25 "CRCW040220R0FKED" 0402L 695.87,1557.14 r0 top value=20.0
R26 "CRCW040220R0FKED" 0402L 707.69,1557.14 r0 bottom value=20.0
R27 "CRCW040220R0FKED" 0402L 633.96,1476.39 r270 top value=20.0
R28 "CRCW040220R0FKED" 0402L 596.2,1501.9 r0 bottom value=20.0
R29 "CRCW040220R0FKED" 0402L 606.39,1408.57 r0 top value=20.0
R30 "CRCW04021K00JNED" 0402 140.47,1714.81 r180 top value=1.0k
R31 "CRCW040222R0JNED" 0402 962.57,1458.6 r180 top value=22
R32 "CRCW08052R70JNEA" 0805L 1440.9,1008.4 r0 bottom value=2.7
R33 "CRCW08052R70JNEA" 0805L 1650.15,1722.01 r90 bottom value=2.7
R34 "CRCW040249R9FKED" 0402 953.59,1560.13 r180 top value=49.9
R35 "CRCW040210K0JNED" 0402 330.88,308.39 r90 top value=10k
R36 "CRCW08052R70JNEA" 0805L 1442.73,1620.63 r0 bottom value=2.7
R37 "CRCW08050000Z0EA" 0805_HV 134.58,1108.7 r270 top value=0
R38 "CRCW040220K0FKED" 0402 539.72,926.03 r180 top value=20.0k
R39 "CRCW040222K0JNED" 0402 334.01,1574.98 r0 top value=22k
R40 "ERJ-2BQFR91X" 0402 372.76,1175.91 r180 top value=0.91
R41 "CRCW0402301KFKED" 0402S 644.97,1087.41 r180 top value=301k
R42 "CRCW0402107KFKED" 0402 664.79,884.34 r90 top value=107k
R43 "CRCW04024K02FKED" 0402 676.6,1017.25 r90 top value=4.02k
R44 "CRCW04021K50JNED" 0402 94.77,1640.98 r180 top value=1.5k
R45 "CRCW08050000Z0EA" 0805_HV 62.1,283.32 r270 top value=0
R46 "CRCW040222R0JNED" 0402 273.63,492.9 r90 bottom value=22
R47 "CRCW040222R0JNED" 0402 314.85,492.9 r90 bottom value=22
R48 "CRCW040222R0JNED" 0402 476.2,496.18 r90 bottom value=22
R49 "CRCW040222R0JNED" 0402 518.34,496.27 r90 bottom value=22
R50 "CRCW060322R0JNEA" 0603 614.66,114.47 r0 top value=22
R51 "CRCW040222R0JNED" 0402 641.32,469.77 r90 bottom value=22
R52 "CRCW040222R0JNED" 0402 786.17,400.52 r0 bottom value=22
R53 "CRCW040222R0JNED" 0402 882.49,400.5 r0 bottom value=22
R54 "CRCW060322R0JNEA" 0603 230.28,494.23 r270 top value=22
R55 "RC0402JR-070RL" 0402 201.21,2121.17 r180 bottom value=0
R56 "CRCW040222R0JNED" 0402S 517.55,1876.92 r270 top value=22
R57 "CRCW040222R0JNED" 0402 705.16,1938.78 r180 top value=22
R58 "CRCW0402150KJNED" 0402 1190.69,2031.92 r90 top value=150k
R59 "CRCW0402100KFKED" 0402 825.53,2303.38 r270 top value=100k
R60 "Resistor" 0402S 1107.64,2364.21 r0 top value=0
R61 "CRCW040224K3FKED" 0402 902.43,2171.37 r180 top value=24.3k
R62 "Resistor" 0402S 1055.46,2383.92 r90 top value=0
R63 "CRCW04024K70JNED" 0402S 1071.72,2491.57 r180 top value=4.7k
R64 "CRCW06031K00FKEA" 0603L 526.22,2233.9 r270 top value=1.00k
R65 "CRCW04024K70JNED" 0402S 362.5,1886.81 r90 top value=4.7k
R66 "CRCW040222R0JNED" 0402S 416.07,1846.5 r90 top value=22
R67 "CRCW04024K70JNED" 0402S 330.2,1996.38 r180 top value=4.7k
R68 "Resistor" 0603S 498.27,2306.16 r180 top value=59.0
R69 "Resistor" 0603S 409.3,2306.16 r180 top value=59.0
R70 "CRCW04024K70JNED" 0402S 613.66,1930.87 r180 top value=4.7k
R71 "CRCW04024K70JNED" 0402S 721.13,2080.88 r270 top value=4.7k
R72 "CRCW06031K00FKEA" 0603L 381.91,2233.9 r90 top value=1.00k
R73 "CRCW04024K70JNED" 0402S 101.41,1890.81 r180 top value=4.7k
R74 "CRCW04024K70JNED" 0402S 44.31,1909.59 r90 top value=4.7k
R75 "CRCW04024K70JNED" 0402S 102.21,1848.63 r180 top value=4.7k
R76 "Resistor" 0603S 243.84,2306.02 r180 top value=59.0
R77 "Resistor" 0603S 154.97,2306.02 r180 top value=59.0
TP1 "5001" Keystone5001 1123.38,1650.76 r90 top
TP2 "TP_SM_1MM" TP_SM_1MM#1 1543.49,475.17 r180 top
TP3 "TP_SM_1MM" TP_SM_1MM#1 1540.38,1074.19 r90 top
TP4 "TP_SM_1MM" TP_SM_1MM#2 1536.61,1677.69 r90 top
TP5 "TP_SM_1MM" TP_SM_1MM#1 1467.57,509.87 r90 top
TP6 "TP_SM_1MM" TP_SM_1MM#1 1458.67,1137.27 r90 top
TP7 "TP_SM_1MM" TP_SM_1MM#1 1448.78,1728.91 r90 top
U1 "INA240A2PWR" PW0008A_L 1033.31,210.8 r180 top
U2 "INA240A2PWR" PW0008A_L 971.39,464.76 r180 top
U3 "INA240A2PWR" PW0008A_L 927.66,644.25 r180 bottom
U4 "TLV431BQDBZRQ1" DBZ0003A_N 589.65,306.29 r270 top
U5 "TMP235DCK" DCK0005A_N 1260.27,232.07 r180 bottom
U6 "DRV8350RSRGZR" RGZ0048L 852.36,1215.62 r90 top
U7 "TI-TPS62162DSG8-1600X900TP" DSG0008A 133.85,939.9 r0 bottom
U8 "LMZM23601SILR" SIL0010A 952.6,2276.19 r180 top
U9 "THVD1550DGKR" DGK0008A_N 453.51,2035.88 r90 top
U10 "TS5A23157DGSR" DGS0010A_L 353.5,1733.06 r0 top
U11 "THVD1550DGKR" DGK0008A_N 200.13,2035.88 r90 top
ZZ1 "This Assembly Note is for PCB labels only" AssemblyNoteLabel 144.41,3889.59 r0 top
ZZ2 "This Assembly Note will show in the PcbDoc and associated outputs" AssemblyNote 144.41,3780.71 r0 top
ZZ3 "This Assembly Note will show in the PcbDoc and associated outputs" AssemblyNote 144.41,3692.15 r0 top
ZZ4 "This Assembly Note will show in the PcbDoc and associated outputs" AssemblyNote 144.41,3603.59 r0 top

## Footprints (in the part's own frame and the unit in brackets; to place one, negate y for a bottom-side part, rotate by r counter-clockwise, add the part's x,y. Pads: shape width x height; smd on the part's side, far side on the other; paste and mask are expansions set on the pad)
0402 [mm] "0402 from SM-752 data"
  rect 0.8x0.6 smd: 1(-0.6,0) 2(0.6,0)
  silkscreen extent -1.22,-0.52 1.22,0.52, body extent -0.55,-0.3 0.55,0.3, height 0.6
0402L [mm] "0402 from SM-752 data"
  rect 0.6x0.5 smd: 1(-0.5,0) 2(0.5,0)
  body extent -0.55,-0.3 0.55,0.3, height 0.6
0402S [mil] "Based on C0402S footprint from PADS legacy"
  rect 15x24 smd: 1(-20,0) 2(20,0)
  body extent -22,-12 22,12, height 24
0603 [mm] "0603 from SM-752 data"
  rect 1x0.95 smd: 1(-0.8,0) 2(0.8,0)
  silkscreen extent -1.52,-0.69 1.52,0.69, body extent -0.87,-0.47 0.87,0.47, height 1
0603L [mm] "0603 from SM-752 data"
  rect 0.8x0.85 smd: 1(-0.7,0) 2(0.7,0)
  silkscreen extent -0.07,-0.33 0.07,0.33, body extent -0.87,-0.47 0.87,0.47, height 1
0603S [mil]
  rect 20x35 smd: 1(-30,0) 2(30,0)
  body extent -34,-19 34,19, height 39
0805_HV [mil] "0805 with 30mil clearance between pads"
  rect 50x63 smd: 1(-40,0) 2(40,0)
  silkscreen extent -74,-40 74,40, body extent -43,-29 43,29, height 57
0805L [mm] "0805 from SM-752 data"
  rect 1.1x1.4 smd: 1(-0.75,0) 2(0.75,0)
  body extent -1.1,-0.72 1.1,0.72, height 1.45
1206 [mm] "1206 from SM-752 data"
  rect 1.3x1.85 smd: 1(-1.45,0) 2(1.45,0)
  silkscreen extent -2.4,-1.21 2.4,1.21, body extent -1.7,-0.9 1.7,0.9, height 1.35
1206_190 [mm] "1206_190"
  rect 1.1x1.6 smd: 1(-1.7,0) 2(1.7,0)
  silkscreen extent -0.9,-1 0.9,1, body extent -1.75,-0.95 1.75,0.95, height 1.9
1210_270 [mm] "1210"
  rect 1.3x2.7 smd: 1(-1.45,0) 2(1.45,0)
  silkscreen extent -2.32,-1.57 2.32,1.57, body extent -1.7,-1.35 1.7,1.35, height 2.7
AssemblyNote [mil] "Assembly Note"
AssemblyNoteLabel [mil] "Assembly Note for PCB Labels"
DBZ0003A_N [mm] "SOT23, 3-Leads, Body 2.9x1.3mm, Pitch 0.95mm, Lead Span 2.4mm, IPC Medium Density"
  rrect17% 1x0.6 smd: 1(-1.2,0.95) 2(-1.2,-0.95) 3(1.2,0)
  silkscreen extent 0.2,-1.5 0.7,1.5, body extent -1.26,-1.46 1.26,1.46, height 0.98
DCK0005A_N [mm] "SOT353, 5-Leads, Body 2x1.3mm, Pitch 0.65mm, Lead Span 2.1mm, IPC Medium Density"
  rrect25% 0.85x0.4 smd: 1(-1.125,0.65) 2(-1.125,0) 3(-1.125,-0.65) 4(1.125,-0.65) 5(1.125,0.65)
  silkscreen extent -0.15,-1.1 0.15,1.1, body extent -1.14,-1 1.14,1, height 0.95
DGK0008A_N [mm] "TSOP, 8-Leads, Body 3x3mm, Pitch 0.65mm, IPC Medium Density"
  oval 1.35x0.4 smd: 1(-2.225,0.975) 2(-2.225,0.325) 3(-2.225,-0.325) 4(-2.225,-0.975) 5(2.225,-0.975) 6(2.225,-0.325) 7(2.225,0.325) 8(2.225,0.975)
  silkscreen extent -2.75,-1.55 0.95,1.55, body extent -2.45,-1.5 2.45,1.5, height 0.96
DGS0010A_L [mm] "TSSOP, 10-Leads, Body 3x3mm, Pitch 0.5mm, IPC High Density"
  oval 1.15x0.25 smd: 1(-2.125,1) 2(-2.125,0.5) 3(-2.125,0) 4(-2.125,-0.5) 5(-2.125,-1) 6(2.125,-1) 7(2.125,-0.5) 8(2.125,0) 9(2.125,0.5) 10(2.125,1)
  silkscreen extent -2.65,-1.55 0.9,1.55, body extent -2.45,-1.5 2.45,1.5, height 0.96
DNK0008A [mm] "SON, 8-Leads, Body 5x6mm"
  rrect39% 0.86x0.51 smd paste-0.05 mask-0.05: 1(-2.82,1.905) 2(-2.82,0.635) 3(-2.82,-0.635) 4(-2.82,-1.905) 5(2.82,-1.905) 6(2.82,-0.635) 7(2.82,0.635) 8(2.82,1.905)
  rrect8% 1.48x1.27 on Top Paste: 9(-0.18,1.47) 9(-0.18,0) 9(-0.18,-1.47) 9(1.5,-1.47) 9(1.5,0) 9(1.5,1.47)
  rrect5% 4.34x4.6 smd paste-3 mask-0.05: 9(1.08,0)
  silkscreen extent -3.2,-2.7 3.2,2.7, body extent -3.05,-2.55 3.05,2.55, height 1.06
DSG0008A [mm] "SON, 8-Leads, Body 2x2mm, Pitch 0.5mm, Thermal Pad 1.6x0.9mm, TI Recommended"
  rrect40% 0.5x0.25 smd: 1(-0.95,0.75) 2(-0.95,0.25) 3(-0.95,-0.25) 4(-0.95,-0.75) 5(0.95,-0.75) 6(0.95,-0.25) 7(0.95,0.25) 8(0.95,0.75)
  rrect14% 0.9x0.7 on Bottom Paste: 9(0,-0.45) 9(0,0.45)
  rrect11% 0.9x1.6 smd paste-0.45: 9(0,0)
  silkscreen extent -1.07,-1.15 1.07,1.15, body extent -1,-1 1,1, height 0.77
FCC_disclaimer [mil]
FCI_89898-310ALF [mm] "Receptacle, 2.54mm, 10x2, SMT"
  rect 1.27x1.57 smd: 1(-11.43,2.815) 2(-11.43,-2.815) 3(-8.89,2.815) 4(-8.89,-2.815) 5(-6.35,2.815) 6(-6.35,-2.815) 7(-3.81,2.815) 8(-3.81,-2.815) 9(-1.27,2.815) 10(-1.27,-2.815) 11(1.27,2.815) 12(1.27,-2.815) 13(3.81,2.815) 14(3.81,-2.815) 15(6.35,2.815) 16(6.35,-2.815) 17(8.89,2.815) 18(8.89,-2.815) 19(11.43,2.815) 20(11.43,-2.815)
  silkscreen extent -12.66,-2.54 12.66,4.42, body extent -12.66,-3.02 12.66,3.02, height 8.2
Fiducial10-20 [mm]
  round 1 smd mask+0.5: 1(0,0)
  Top Layer keep-out circle w1.178: c0,0 r0.5
IEC_HotSurface_Small [mil]
  silkscreen extent -107,-93 107,92
Keystone5001 [mil] "For Keystone 500x miniature loop terminals"
  round 80 hole 40: 1(0,0)
  silkscreen extent -52,-52 52,52, body extent -49,-49 49,49, height 182
KYB_1250x2000 [mm] "TH, 2-Leads, Dia 12.5mm, Lead Spacing 5mm"
  rrect50% 1.275x1.275 hole 0.85: 1(-2.5,0)
  round 1.275 hole 0.85: 2(2.5,0)
  body extent -6.5,-6.5 6.51,6.5, height 21.51
Label_650x200 [mil] "Thermal Transfer Label"
  round 1 on Mech13: 0(0,0)
  silkscreen extent -325,-100 325,100, body extent -325,-100 325,100, height 1
Molex_90121-0766 [mm] "Header, 2.54mm, 6x1, R/A, TH"
  rect 1.5x1.5 hole 1: 1(-6.35,0)
  round 1.5 hole 1: 2(-3.81,0) 3(-1.27,0) 4(1.27,0) 5(3.81,0) 6(6.35,0)
  silkscreen extent -8,-4.25 7.62,-2.25, body extent -7.62,-11 7.62,0.32, height 3.63
MSS7348 [mm] "SMD, 2-Leads, Body 7x7mm"
  rrect6% 1.6x2.2 smd: 1(-3,0) 2(3,0)
  silkscreen extent -3.75,-3.75 3.75,3.75, body extent -3.66,-3.66 3.66,3.66, height 4.7
Net-Tie_10milWide_30milLong#1 [mil] "10mil net tie, no solder mask opening, no solder paste"
  rect 30x10 smd paste-5 mask-5: 1(-15,0) 2(15,0)
Net-Tie_10milWide_30milLong#2 [mil] "10mil net tie, no solder mask opening, no solder paste"
  rect 30x10 on Mid2 paste-5 mask-5: 1(-15,0) 2(15,0)
NLCV25 [mm] "TDK"
  rect 1x1.5 smd: 1(-1.25,0) 2(1.25,0)
  body extent -1.35,-1.05 1.35,1.05, height 1.9
Pb-Free_Overlay_Small [mil]
  silkscreen extent -46,-46 46,46
PowerDI123 [mm] "Diodes Inc recommended land pattern, document number DS30628 Rev. 6-2"
  rect 2.2x1.4 smd: 1(-1.275,0)
  rect 0.9x1.4 smd: 2(1.275,0)
  silkscreen extent -3.1,-1.09 1.76,1.09, body extent -2.38,-0.97 1.52,0.96, height 1
PW0008A_L [mm] "TSOP, 8-Leads, Body 3x4.4mm, Pitch 0.65mm, IPC High Density"
  oval 1.2x0.4 smd: 1(-2.85,0.975) 2(-2.85,0.325) 3(-2.85,-0.325) 4(-2.85,-0.975) 5(2.85,-0.975) 6(2.85,-0.325) 7(2.85,0.325) 8(2.85,0.975)
  silkscreen extent -3.2,-1.55 1.85,1.55, body extent -3.21,-1.5 3.21,1.5, height 1.2
RGZ0048L [mm] "QFN, 48-Leads, Body 7x7mm, Pitch 0.5mm, Thermal Pad 4.975x4.6mm, TI Recommended"
  rrect42% 0.6x0.24 smd: 1(-3.4,2.75) 2(-3.4,2.25) 3(-3.4,1.75) 4(-3.4,1.25) 5(-3.4,0.75) 6(-3.4,0.25) 7(-3.4,-0.25) 8(-3.4,-0.75) 9(-3.4,-1.25) 10(-3.4,-1.75) 11(-3.4,-2.25) 12(-3.4,-2.75) 25(3.4,-2.75) 26(3.4,-2.25) 27(3.4,-1.75) 28(3.4,-1.25) 29(3.4,-0.75) 30(3.4,-0.25) 31(3.4,0.25) 32(3.4,0.75) 33(3.4,1.25) 34(3.4,1.75) 35(3.4,2.25) 36(3.4,2.75)
  rrect42% 0.24x0.6 smd: 13(-2.75,-3.4) 14(-2.25,-3.4) 15(-1.75,-3.4) 16(-1.25,-3.4) 17(-0.75,-3.4) 18(-0.25,-3.4) 19(0.25,-3.4) 20(0.75,-3.4) 21(1.25,-3.4) 22(1.75,-3.4) 23(2.25,-3.4) 24(2.75,-3.4) 37(2.75,3.4) 38(2.25,3.4) 39(1.75,3.4) 40(1.25,3.4) 41(0.75,3.4) 42(0.25,3.4) 43(-0.25,3.4) 44(-0.75,3.4) 45(-1.25,3.4) 46(-1.75,3.4) 47(-2.25,3.4) 48(-2.75,3.4)
  rrect8% 1.37x1.28 on Top Paste: 49(-1.382,1.48) 49(-1.382,0) 49(-1.382,-1.48) 49(0.188,1.48) 49(0.188,0) 49(0.188,-1.48) 49(1.758,-1.48) 49(1.758,0) 49(1.758,1.48)
  rrect2% 4.975x4.6 smd paste-2.575: 49(0.188,0)
  silkscreen extent -3.65,-3.65 3.65,3.65, body extent -3.5,-3.5 3.5,3.5, height 1
SIL0010A [mm] "MicoSiP, TI recommended land pattern"
  rrect50% 0.65x0.3 smd paste+0 mask+0.05: 1(-1.525,1.2) 2(-1.525,0.6) 3(-1.525,0) 4(-1.525,-0.6) 5(-1.525,-1.2) 6(1.525,-1.2) 7(1.525,-0.6) 8(1.525,0) 9(1.525,0.6) 10(1.525,1.2)
  rrect14% 0.7x0.833 on Top Paste: 11(-0.175,1.03) 11(-0.175,0) 11(-0.175,-1.03)
  rrect25% 0.8x3 smd paste-0.5 mask-0.05: 11(-0.175,0)
  silkscreen extent -1.9,-1.68 1.9,1.68, body extent -1.9,-1.5 1.9,1.5, height 1.49
SOT-23 [mm] "SOT23, 3-Leads, Body 2.9x1.3mm, Pitch 0.95mm, Lead Span 2.5mm, IPC Medium Density"
  rrect50% 1x0.6 smd: 1(-1.2,0.95) 2(-1.2,-0.95) 3(1.2,0)
  silkscreen extent -1.62,-1.5 0.7,1.5, body extent -1.16,-1.45 1.21,1.45, height 1
TP_SM_1MM#1 [mm] "1mm Test Point, SMT"
  round 1 smd paste-0.5: 1(0,0)
TP_SM_1MM#2 [mm] "1mm Test Point, SMT"
  round 1 smd paste-0.5 mask-0.025: 1(0,0)
WEEE_Minimum [mil] "WEEElie bin"
  silkscreen extent -95,-172 99,104
WL-SMCW_GREEN [mm] "WURTH"
  rect 0.8x0.8 smd: 1(-0.8,0) 2(0.8,0)
  silkscreen extent -1.9,-0.8 1.2,0.8, body extent -0.85,-0.45 0.85,0.45, height 0.8
Wurth_61000218321 [mm] "Header, 2.54mm, 2x1, SMT"
  rect 1x3 smd: 1(-1.27,1.5) 2(1.27,-1.5)
  silkscreen extent -2.86,-1.27 2.54,1.27, body extent -2.54,-2.5 2.54,2.5, height 6.3
Wurth_61000318221 [mm] "Header, 2.54mm, 3x1, SMT"
  rrect10% 3x1 smd: 1(-1.4,2.54) 2(1.6,0) 3(-1.4,-2.54)
  body extent -2.5,-3.81 2.5,3.81, height 9.33
Wurth_691236510002 [mm] "Terminal Block, 5.08mm, 2x1, R/A, TH"
  rrect50% 2.25x2.25 hole 1.5: 1(-2.54,0)
  round 2.25 hole 1.5: 2(2.54,0)
  body extent -5.68,-5.5 5.08,5.85, height 18
Wurth_691236510003 [mm] "Terminal Block, 5.08mm, 3x1, R/A, TH"
  rrect50% 2.25x2.25 hole 1.5: 1(-5.08,0)
  round 2.25 hole 1.5: 2(0,0) 3(5.08,0)
  body extent -8.22,-5.5 7.62,5.85, height 18
XFL3012 [mm] "Coilcraft"
  rect 1.12x3.2 smd: 1(-1.11,0) 2(1.11,0)
  body extent -1.6,-1.6 1.6,1.6, height 1.3

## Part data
C1 C3 C5 C6 C8 C9 C12 C55: library part CMP-0006228-2, "CAP, CERM, 0.1 uF, 16 V, +/- 10%, X7R, 0402", Cap_Case=0402, Manufacturer="Wurth Elektronik", Supplier Part Number 1=732-7532-1-ND, TempCo=X7R, Tolerance_%=10%, Value1=Unknown, Value2=16V, ValueDisplayed=0.1uF
C2 C4 C7 C10: library part CMP-0006629-2, "CAP, CERM, 0.1 uF, 10 V, +/- 10%, X7R, 0402", Cap_Case=0402, Manufacturer=MuRata, Supplier Part Number 1=GRM155R71A104KA01D-ND, TempCo=X7R, Tolerance_%=10%, Value1=Unknown, Value2=10V, ValueDisplayed=0.1uF
C11: library part CMP-0007696-2, "CAP, CERM, 1 uF, 50 V, +/- 10%, X7R, 0805", Cap_Case=0805, Manufacturer="Wurth Elektronik", Supplier Part Number 1=710-885012207103, TempCo=X7R, Tolerance_%=10%, Value1=Unknown, Value2=50V, ValueDisplayed=1uF
C13: library part CMP-0006358-2, "CAP, CERM, 0.022 uF, 50 V, +/- 10%, C0G/NP0, 0402", Cap_Case=0402, Manufacturer=MuRata, Supplier Part Number 1=490-4763-1-ND, TempCo=C0G/NP0, Tolerance_%=10%, Value1=Unknown, Value2=50V, ValueDisplayed=0.022uF
C14: library part CMP-0079802-1, "CAP, AL, 180 µF, 100 V, +/- 20%, TH", Cap_Case=12.5x20mm, Manufacturer=Chemi-Con, Supplier Part Number 1=565-4016-ND, Tolerance_%=20%, Value2=100V, ValueDisplayed=180µF
C15 C16: library part CMP-0009231-2, "CAP, CERM, 1 uF, 100 V, +/- 10%, X7R, 1210", Cap_Case=1210, Manufacturer=MuRata, Supplier Part Number 1=490-1857-1-ND, TempCo=X7R, Tolerance_%=10%, Value1=Unknown, Value2=100V, ValueDisplayed=1uF
C17: library part CMP-0007350-5, "CAP, CERM, 1 uF, 50 V, +/- 10%, X5R, 0603", Cap_Case=0603, Manufacturer=MuRata, Supplier Part Number 1=13T1194, TempCo=X5R, Tolerance_%=10%, Value1=Unknown, Value2=50V, ValueDisplayed=1uF
C18 C26 C28 C33 C40 C46: library part CMP-0007475-4, "CAP, CERM, 2200 pF, 100 V, +/- 10%, X7R, 0603", Cap_Case=0603, Manufacturer=MuRata, Supplier Part Number 1=490-1478-1-ND, TempCo=X7R, Tolerance_%=10%, Value1=Unknown, Value2=100V, ValueDisplayed=2200pF
C19 C21 C29 C31 C41 C43: library part CMP-0009232-2, "CAP, CERM, 2.2 uF, 100 V, +/- 10%, X7R, 1210", Cap_Case=1210, Manufacturer=MuRata, Supplier Part Number 1=490-3385-1-ND, TempCo=X7R, Tolerance_%=10%, Value1="0.007 ohm", Value2=100V, ValueDisplayed=2.2uF
C20 C22 C30 C32 C42 C44 C51: library part CMP-0007470-5, "CAP, CERM, 0.1 uF, 100 V, +/- 10%, X7R, 0603", Cap_Case=0603, Manufacturer=MuRata, Supplier Part Number 1=490-6439-1-ND, TempCo=X7R, Tolerance_%=10%, Value1=Unknown, Value2=100V, ValueDisplayed=0.1uF
C23 C67: library part CMP-0008378-2, "CAP, CERM, 10 uF, 25 V, +/- 10%, X7R, 0805", Cap_Case=0805, Manufacturer=MuRata, Supplier Part Number 1=81-GRM21BZ71E106KE5L, TempCo=X7R, Tolerance_%=10%, Value1=Unknown, Value2=25V, ValueDisplayed=10uF
C24: library part CMP-0006659-2, "CAP, CERM, 0.1 uF, 25 V, +/- 10%, X7R, 0402", Cap_Case=0402, Manufacturer=MuRata, Supplier Part Number 1=490-10698-1-ND, TempCo=X7R, Tolerance_%=10%, Value1=Unknown, Value2=25V, ValueDisplayed=0.1uF
C25: library part CMP-0008373-2, "CAP, CERM, 0.047 uF, 100 V, +/- 10%, X7R, 0805", Cap_Case=0805, Manufacturer=MuRata, Supplier Part Number 1=490-3325-1-ND, TempCo=X7R, Tolerance_%=10%, Value1=Unknown, Value2=100V, ValueDisplayed=0.047uF
C27: library part CMP-0006624-2, "CAP, CERM, 1 uF, 6.3 V, +/- 20%, X7R, 0402", Cap_Case=0402, Manufacturer=MuRata, Supplier Part Number 1=490-9665-1-ND, TempCo=X7R, Tolerance_%=20%, Value1=Unknown, Value2=6.3V, ValueDisplayed=1uF
C34 C35 C36 C37 C38 C39: library part CMP-0006214-2, "CAP, CERM, 47 pF, 50 V, +/- 5%, C0G/NP0, 0402", Cap_Case=0402, Manufacturer="Wurth Elektronik", Supplier Part Number 1=732-7459-1-ND, TempCo=C0G/NP0, Tolerance_%=5%, Value1=Unknown, Value2=50V, ValueDisplayed=47pF
C45: library part CMP-0006217-2, "CAP, CERM, 100 pF, 50 V, +/- 5%, C0G/NP0, 0402", Cap_Case=0402, Manufacturer="Wurth Elektronik", Supplier Part Number 1=732-7475-1-ND, TempCo=C0G/NP0, Tolerance_%=5%, Value1=Unknown, Value2=50V, ValueDisplayed=100pF
C47: library part CMP-0007468-5, "CAP, CERM, 0.01 uF, 100 V, +/- 10%, X7R, 0603", Cap_Case=0603, Manufacturer=MuRata, Supplier Part Number 1=GRM188R72A103KA01D-ND, TempCo=X7R, Tolerance_%=10%, Value1=Unknown, Value2=100V, ValueDisplayed=0.01uF
C48: library part CMP-0007207-4, "CAP, CERM, 3000 pF, 50 V, +/- 5%, C0G/NP0, 0603", Cap_Case=0603, Manufacturer=MuRata, Supplier Part Number 1=GRM1885C1H302JA01D-ND, TempCo=C0G/NP0, Tolerance_%=5%, Value1=Unknown, Value2=50V, ValueDisplayed=3000pF
C49: library part CMP-0007877-2, "CAP, CERM, 2.2 uF, 50 V, +/- 10%, X7R, 0805", Cap_Case=0805, Manufacturer=TDK, Supplier Part Number 1=445-5968-1-ND, TempCo=X7R, Tolerance_%=10%, Value1="0.00366 ohm", Value2=50V, ValueDisplayed=2.2uF
C50 C52: library part CMP-0008725-2, "CAP, CERM, 3.3 uF, 100 V, +/- 20%, X7S, 1206_190", Cap_Case=1206_190, Manufacturer=TDK, PartNumber=C3216X7S2A335M160AB, Supplier Part Number 1=445-9234-1-ND, TempCo=X7S, Tolerance_%=20%, Value1="0.003048 ohm", Value2=100V, ValueDisplayed=3.3uF
C53: library part CMP-0007469-4, "CAP, CERM, 0.1 uF, 100 V, +/- 10%, X7R, 0603", Cap_Case=0603, Manufacturer=MuRata, PartNumber=GRM188R72A104KA35D, Supplier Part Number 1=490-3285-1-ND, TempCo=X7R, Tolerance_%=10%, Value1=Unknown, Value2=100V, ValueDisplayed=0.1uF
C54: library part CMP-0007508-5, "CAP, CERM, 1 uF, 50 V, +/- 10%, X7R, 0603", Cap_Case=0603, Manufacturer="Taiyo Yuden", Supplier Part Number 1=587-3247-1-ND, TempCo=X7R, Tolerance_%=10%, Value1=Unknown, Value2=50V, ValueDisplayed=1uF
C56: library part CMP-0007691-2, "CAP, CERM, 10 uF, 10 V, +/- 10%, X7R, 0805", Cap_Case=0805, Manufacturer="Wurth Elektronik", Supplier Part Number 1=710-885012207026, TempCo=X7R, Tolerance_%=10%, Value1=Unknown, Value2=10V, ValueDisplayed=10uF
C57: library part CMP-0007007-5, "CAP, CERM, 10 uF, 25 V, +/- 20%, X5R, 0603", Cap_Case=0603, Manufacturer=TDK, PartNumber=C1608X5R1E106M080AC, Supplier Part Number 1=445-9015-1-ND, TempCo=X5R, Tolerance_%=20%, Value1="0.004639 ohm", Value2=25V, ValueDisplayed=10uF
C58: library part CMP-0007158-5, "CAP, CERM, 22 uF, 10 V, +/- 20%, X5R, 0603", Cap_Case=0603, Manufacturer=MuRata, PartNumber=GRM187R61A226ME15D, Supplier Part Number 1=490-13243-1-ND, TempCo=X5R, Tolerance_%=20%, Value1=Unknown, Value2=10V, ValueDisplayed=22uF
C59 C60 C61 C62 C63 C64 C65 C66: library part CMP-0006646-2, "CAP, CERM, 2200 pF, 16 V, +/- 10%, X7R, 0402", Cap_Case=0402, Manufacturer=MuRata, Supplier Part Number 1=GRM155R71C222KA01D-ND, TempCo=X7R, Tolerance_%=10%, Value1=Unknown, Value2=16V, ValueDisplayed=2200pF
C68: library part CMP-0009224-2, "CAP, CERM, 22 uF, 25 V, +/- 10%, X7R, 1210", Cap_Case=1210, Manufacturer=MuRata, Supplier Part Number 1=490-5313-1-ND, TempCo=X7R, Tolerance_%=10%, Value1=Unknown, Value2=25V, ValueDisplayed=22uF
C69 C70 C72: library part CMP-0006228-2, "CAP, CERM, 0.1 uF, 16 V, +/- 10%, X7R, 0402", Cap_Case=0402, Manufacturer="Wurth Elektronik", PartNumber=885012205037, Supplier Part Number 1=732-7532-1-ND, TempCo=X7R, Tolerance_%=10%, Value1=Unknown, Value2=16V, ValueDisplayed=0.1uF
C71 C73: library part CMP-0006834-5, "CAP, CERM, 470 pF, 50 V, +/- 10%, X7R, 0603", Cap_Case=0603, Manufacturer="Wurth Elektronik", PartNumber=885012206081, Supplier Part Number 1=710-885012206081, TempCo=X7R, Tolerance_%=10%, Value1=Unknown, Value2=50V, ValueDisplayed=470pF
C74 C75 C76 C77 C78 C79: library part CMP-0007159-4, "CAP, CERM, 1000 pF, 25 V, +/- 5%, C0G/NP0, 0603", Cap_Case=0603, Manufacturer=MuRata, Supplier Part Number 1=GRM1885C1E102JA01D-ND, TempCo=C0G/NP0, Tolerance_%=5%, Value1=Unknown, Value2=25V, ValueDisplayed=1000pF
D1 D2: library part CMP-0028517-1, "Diode, Schottky, 200 V, 1 A, PowerDI123", Manufacturer="Diodes Inc.", Supplier Part Number 1=DFLS1200DICT-ND, Value1=1A, Value2=0.85V
D3 D4 D7: library part CMP-0002905-1, "LED, Green, SMD", Color=Green, Manufacturer="Wurth Elektronik", PartNumber=150060GS75000, Supplier Part Number 1=732-4971-1-ND, Value1=W, Value2=3.2V
D5 D6: library part CMP-0028453-1, "Diode, Schottky, 30 V, 0.2 A, SOT-23", Manufacturer="Diodes Inc.", Supplier Part Number 1=BAT54C-FDICT-ND, Value1=0.2A, Value2=0.65V
FID1 FID2 FID3 FID4 FID5 FID6: library part CMP-0077181-1, "Fiducial mark.  There is nothing to buy or mount.", Manufacturer=N/A
J1: library part CMP-0054787-1, "Header, 2.54mm, 2x1, Gold, SMT", Color=Black, Manufacturer="Wurth Elektronik"
J2 J3: library part CMP-0055772-1, "Receptacle, 2.54mm, 10x2, Gold, SMT", Color=Grey, Current_A=3A, Manufacturer=FCI, Supplier Part Number 1=609-4473-1-ND, Voltage_V=1kV
J4: library part CMP-0079473-1, "Header, 2.54mm, 3x1, Gold, SMT", Color=Black, Current_A=3A, Manufacturer="Wurth Elektronik", Voltage_V=250V
J5: library part CMP-0079044-1, "Terminal Block, 5.08mm, 2x1, R/A, TH", Color=Green, Current_A=20A, Manufacturer="Wurth Elektronik", Supplier Part Number 1=732-10995-ND, Voltage_V=300V
J6: library part CMP-0079043-1, "Terminal Block, 5.08mm, 3x1, R/A, TH", Color=Green, Current_A=20A, Manufacturer="Wurth Elektronik", Supplier Part Number 1=732-10996-ND, Voltage_V=300V
J7: library part CMP-0055334-1, "Header, 2.54mm, 6x1, Gold, R/A, TH", Color=Black, Current_A=3A, Manufacturer=Molex, Supplier Part Number 1=WM8112-ND, Voltage_V=350V
L1 L6: library part CMP-0003183-2, "Ferrite Bead, 100 ohm @ 100 MHz, 0.5 A, 0603", Manufacturer="Wurth Elektronik", Supplier Part Number 1=732-1579-1-ND, Value1="0.15 ohm", Value2=0.5A, ValueDisplayed="100 ohm"
L2: library part CMP-0077440-1, "Inductor, Shielded, Ferrite, 220 µH, .5 A, .624 ohm, SMD", Manufacturer=Coilcraft, Supplier Part Number 1=994-MSS7348-224MEB, Value1=".624 ohm", Value2=.5A, ValueDisplayed=220µH
L3: library part CMP-0062507-2, "Inductor, Shielded, Ferrite, 33 uH, 0.085 A, 1.4 ohm, SMD", Manufacturer=TDK, PartNumber=NLFV25T-330K-PF, Supplier Part Number 1=445-1908-1-ND, Value1="1.4 ohm", Value2=0.085A, ValueDisplayed=33uH
L4: library part CMP-0003215-1, "Ferrite Bead, 100 ohm @ 100 MHz, 0.2 A, 0402", Manufacturer="Wurth Elektronik", Supplier Part Number 1=732-2361-1-ND, Value1="0.3 ohm", Value2=0.2A, ValueDisplayed="100 ohm"
L5: library part CMP-0061137-1, "Inductor, Shielded, Composite, 2.2 uH, 1.6 A, 0.08 ohm, SMD", Manufacturer=Coilcraft, PartNumber=XFL3012-222MEB, Value1="0.08 ohm", Value2=1.6A, ValueDisplayed=2.2uH
LBL1: library part CMP-0003625-1, "Thermal Transfer Printable Labels, 0.650\" W x 0.200\" H - 10,000 per roll", Manufacturer=Brady, PartNumber=THT-14-423-10, Supplier Part Number 1=97C5133
LOGO1 LOGO2: library part CMP-0074837-1, "IEC 61010-1 Hot Surface Warning"
Logo4: library part CMP-0074839-1
Logo5: library part CMP-0074847-1, "FCC_disclaimer"
Logo6: library part CMP-0074769-1
NT1 NT2 NT3 NT4 NT5 NT6 NT7: library part CMP-0078142-1, "Single point connection between nets.", Manufacturer=N/A
Q1 Q2 Q3 Q4 Q5 Q6: library part CMP-0000958-2, "MOSFET, N-CH, 100 V, 17 A, DNK0008A (VSON-CLIP-8)", Alternate Manufacturer=None, Manufacturer="Texas Instruments", Supplier Part Number 1=296-37478-6-ND, Value2="48 nC"
R1 R3 R8 R12 R21 R59: library part CMP-0025950-3, "RES, 100 k, 1%, 0.063 W, AEC-Q200 Grade 0, 0402", Manufacturer=Vishay-Dale, Power_W=63mW, Supplier Part Number 1=541-100KLCT-ND, TempCo="100 ppm/C", Tolerance_%=1%, Value2=0.063W, Value_Code=100k
R2 R7 R11: library part CMP-0078821-1, "RES, 0.001, 1%, 1 W, AEC-Q200 Grade 0, 1206", Manufacturer=Bourns, Power_W=1W, TempCo="50 ppm/C", Tolerance_%=1%, Value_Code=1L000, ValueDisplayed=0.001
R4 R6 R10 R17: library part CMP-0026334-2, "RES, 3.40 k, 1%, 0.063 W, AEC-Q200 Grade 0, 0402", Manufacturer=Vishay-Dale, Power_W=63mW, Supplier Part Number 1=541-3.40KLCT-ND, TempCo="100 ppm/C", Tolerance_%=1%, Value2=0.063W, Value_Code=3k40, ValueDisplayed=3.40k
